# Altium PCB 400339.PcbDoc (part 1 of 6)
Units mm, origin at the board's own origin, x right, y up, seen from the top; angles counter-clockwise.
Board outline 146 x 63.5 mm, 4 copper layers (Top Layer, Mid-Layer 1, Mid-Layer 2, Bottom Layer), stack 1.505 mm thick; 400 components, 261 nets, 1523 pads, 1938 vias.
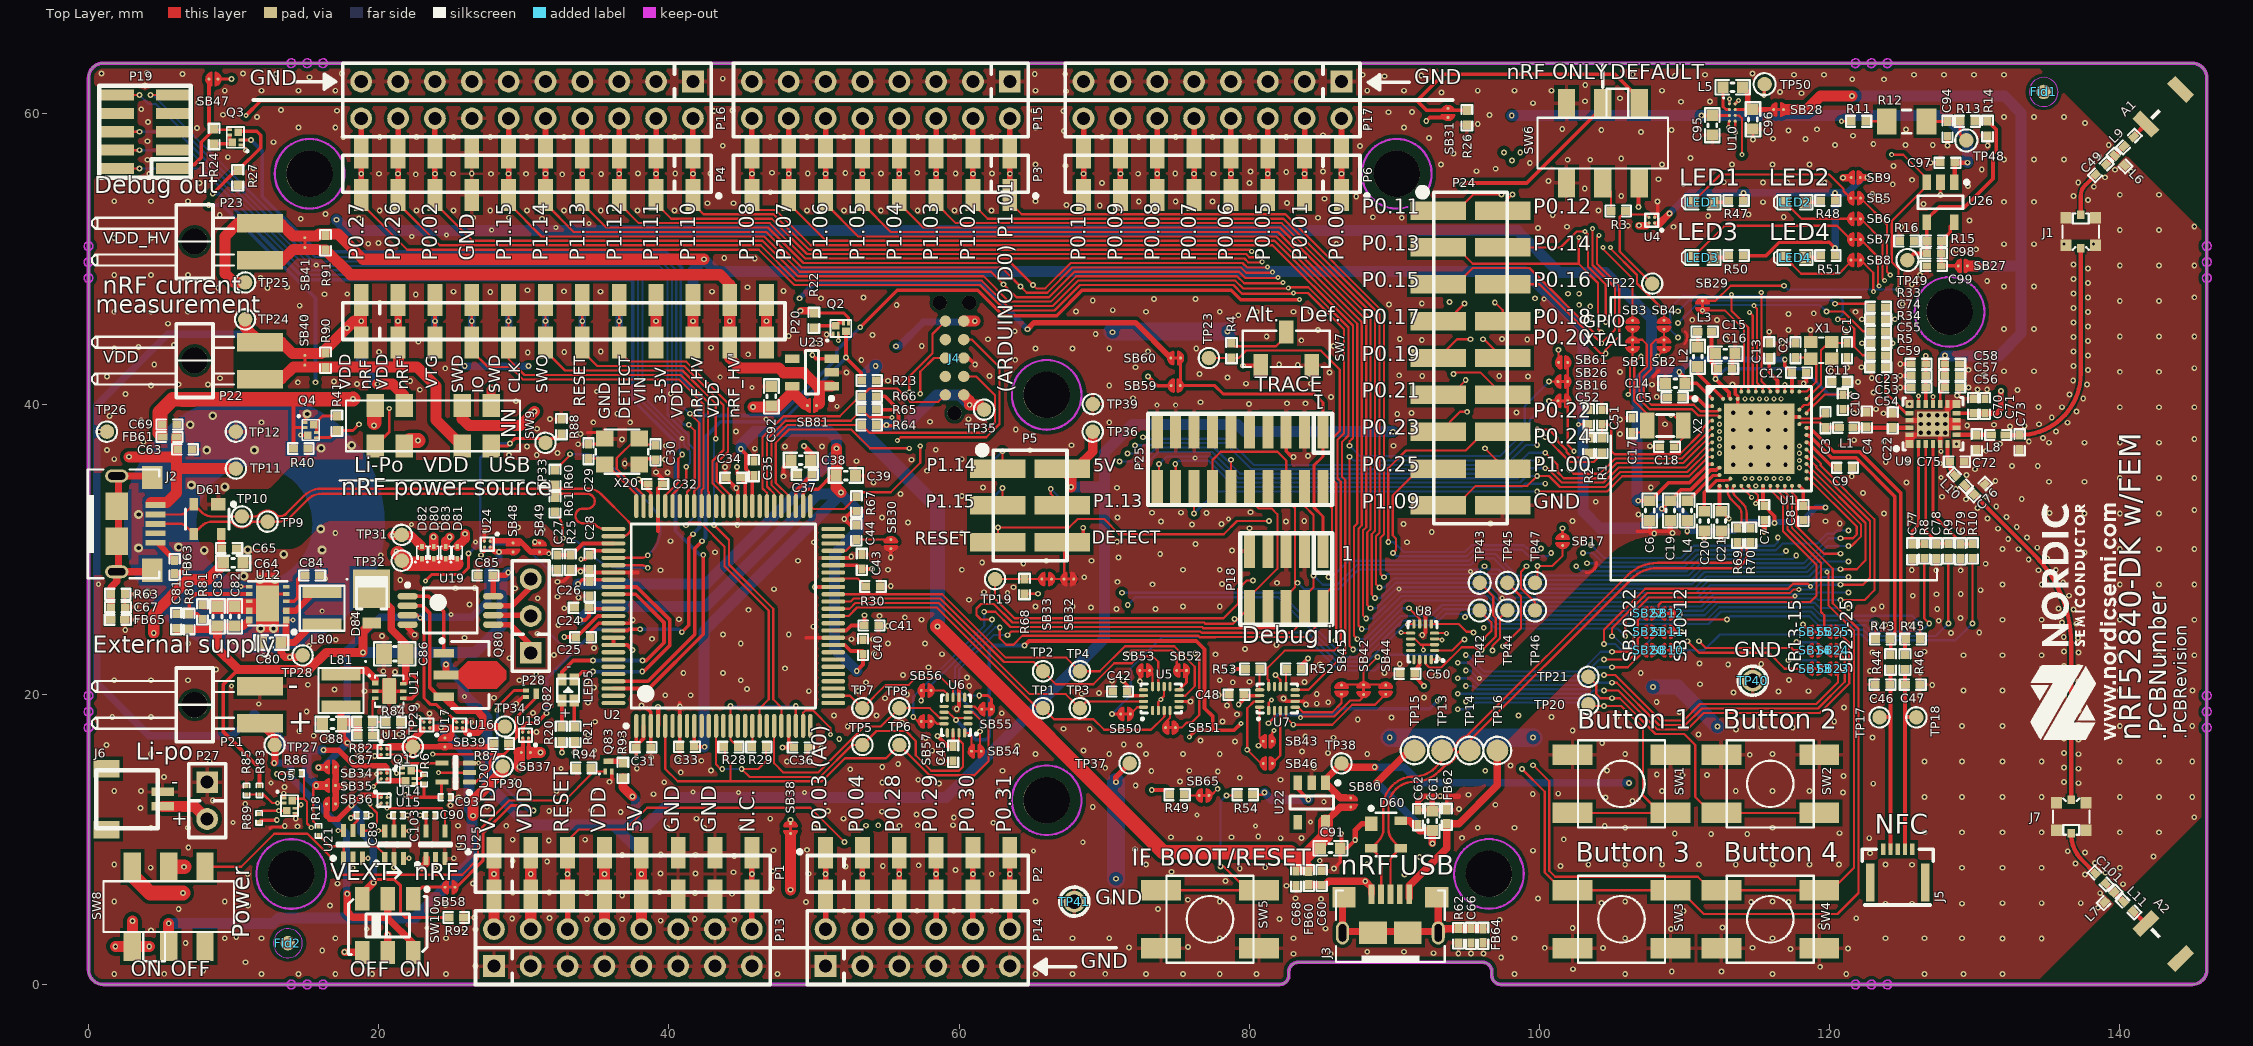
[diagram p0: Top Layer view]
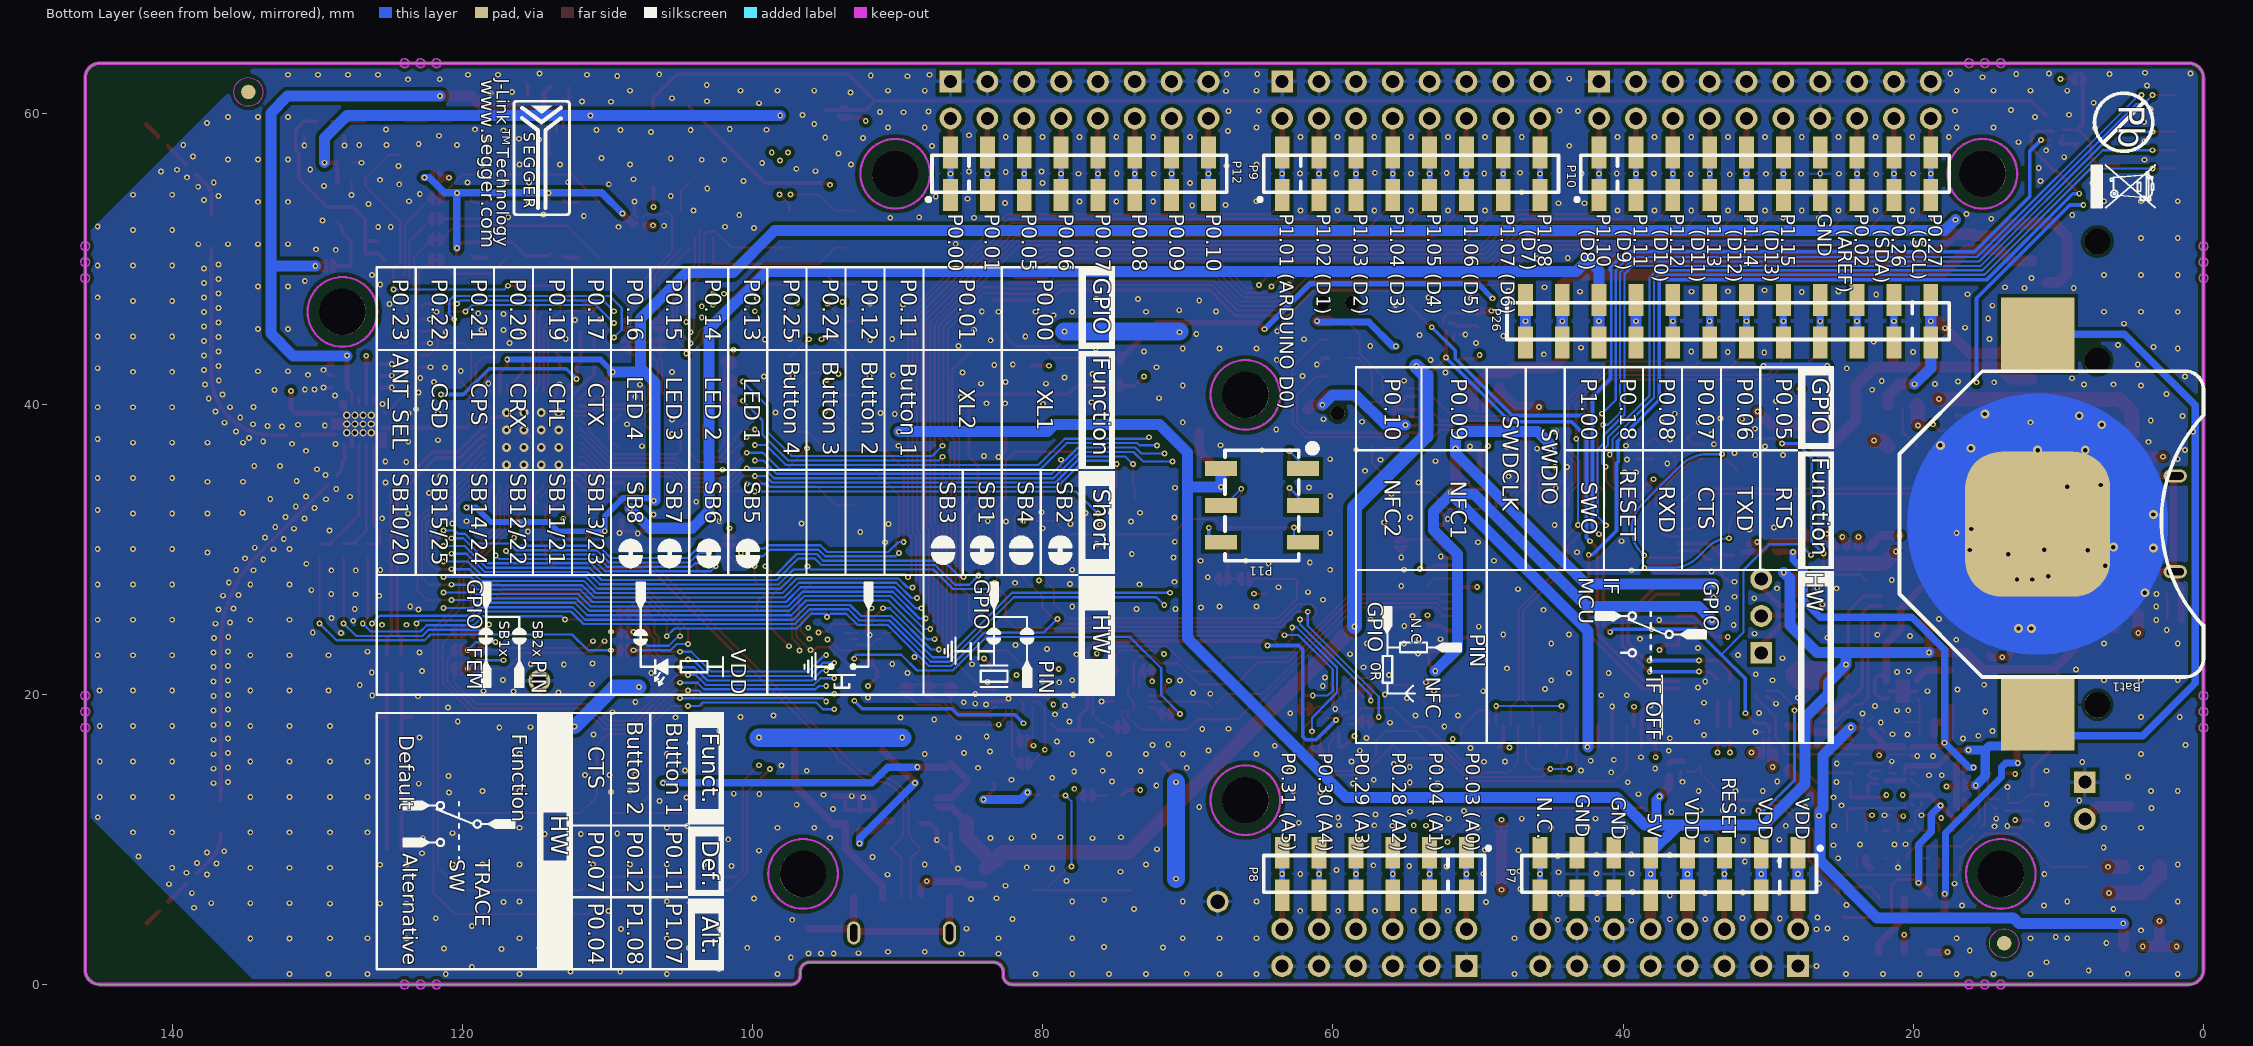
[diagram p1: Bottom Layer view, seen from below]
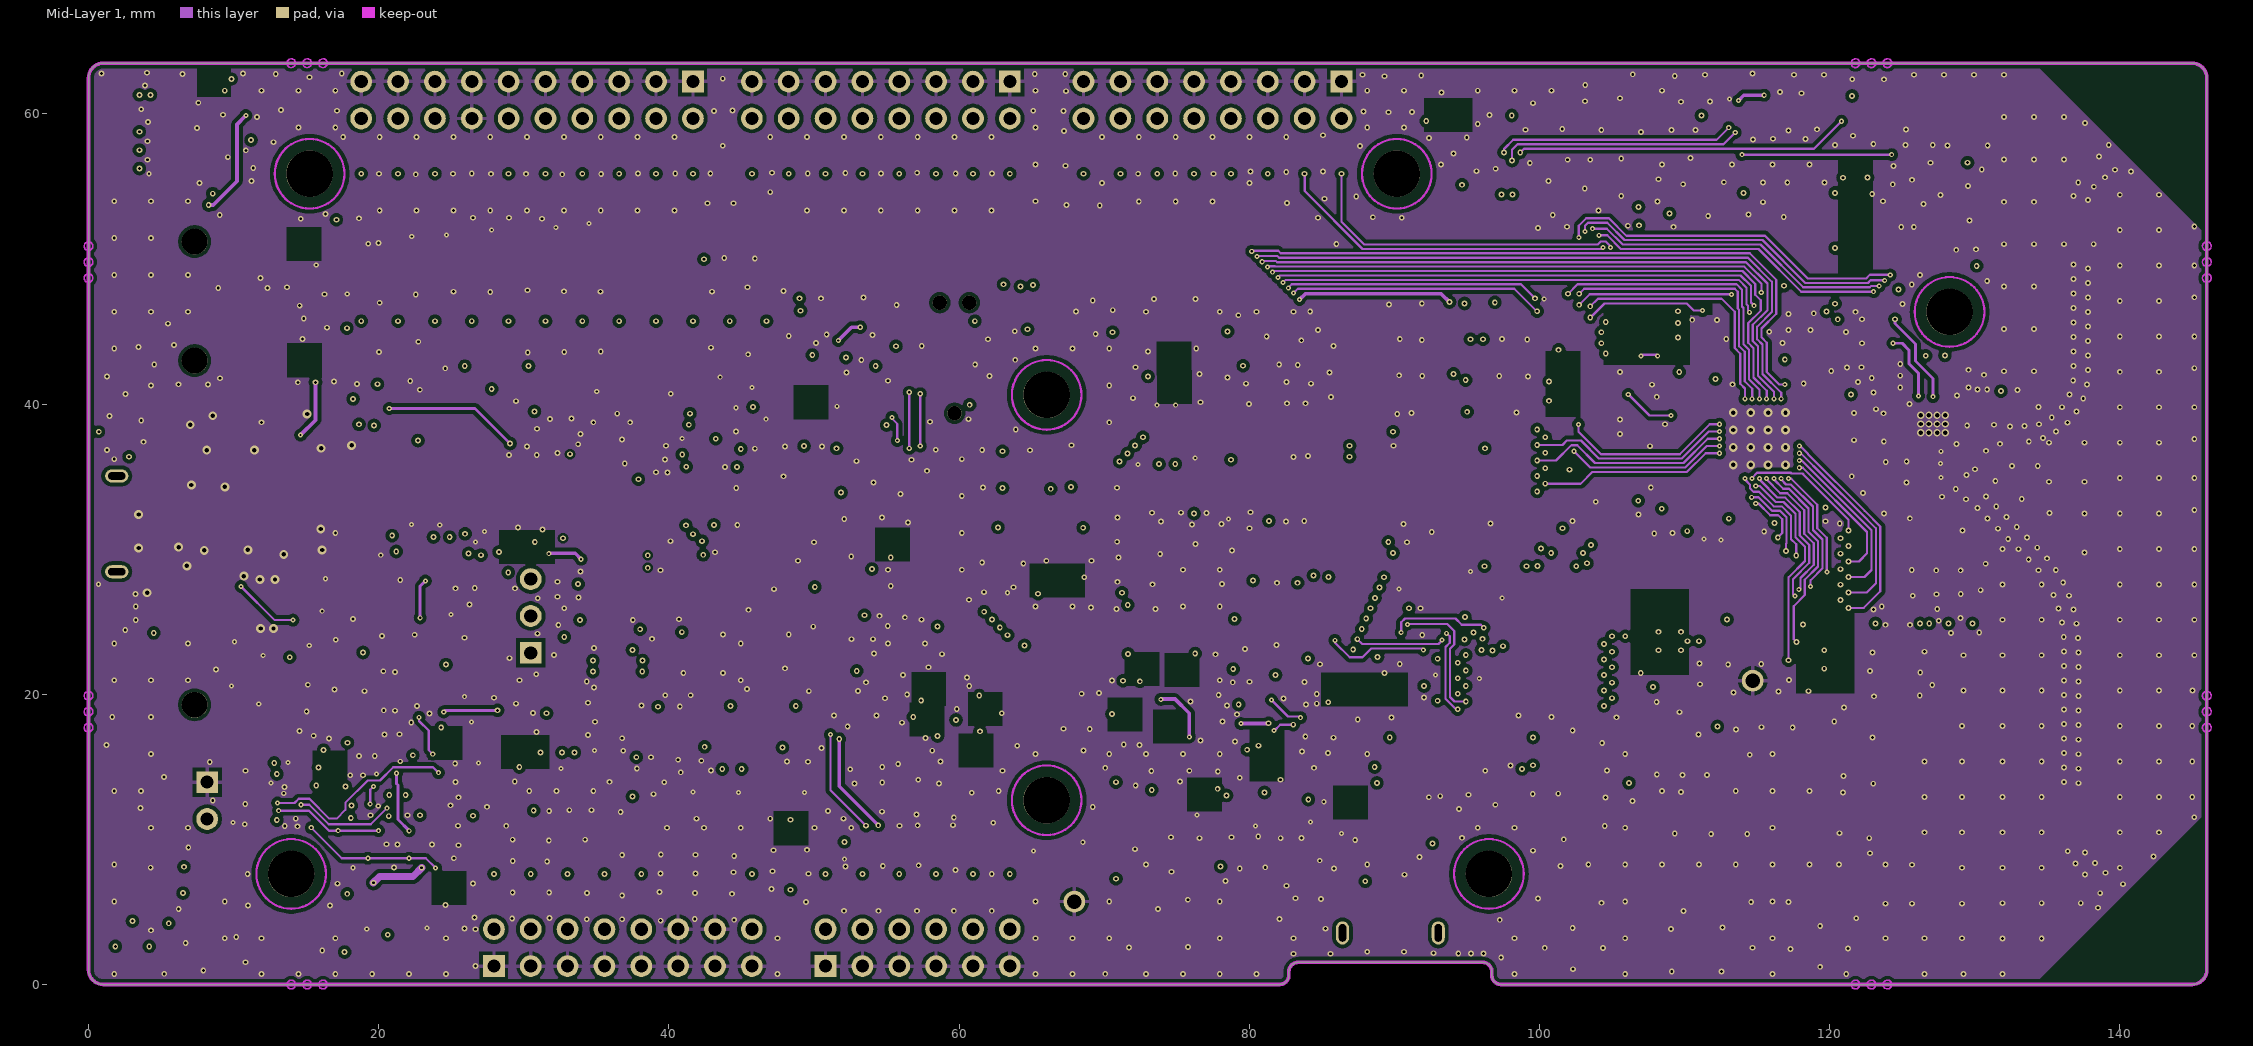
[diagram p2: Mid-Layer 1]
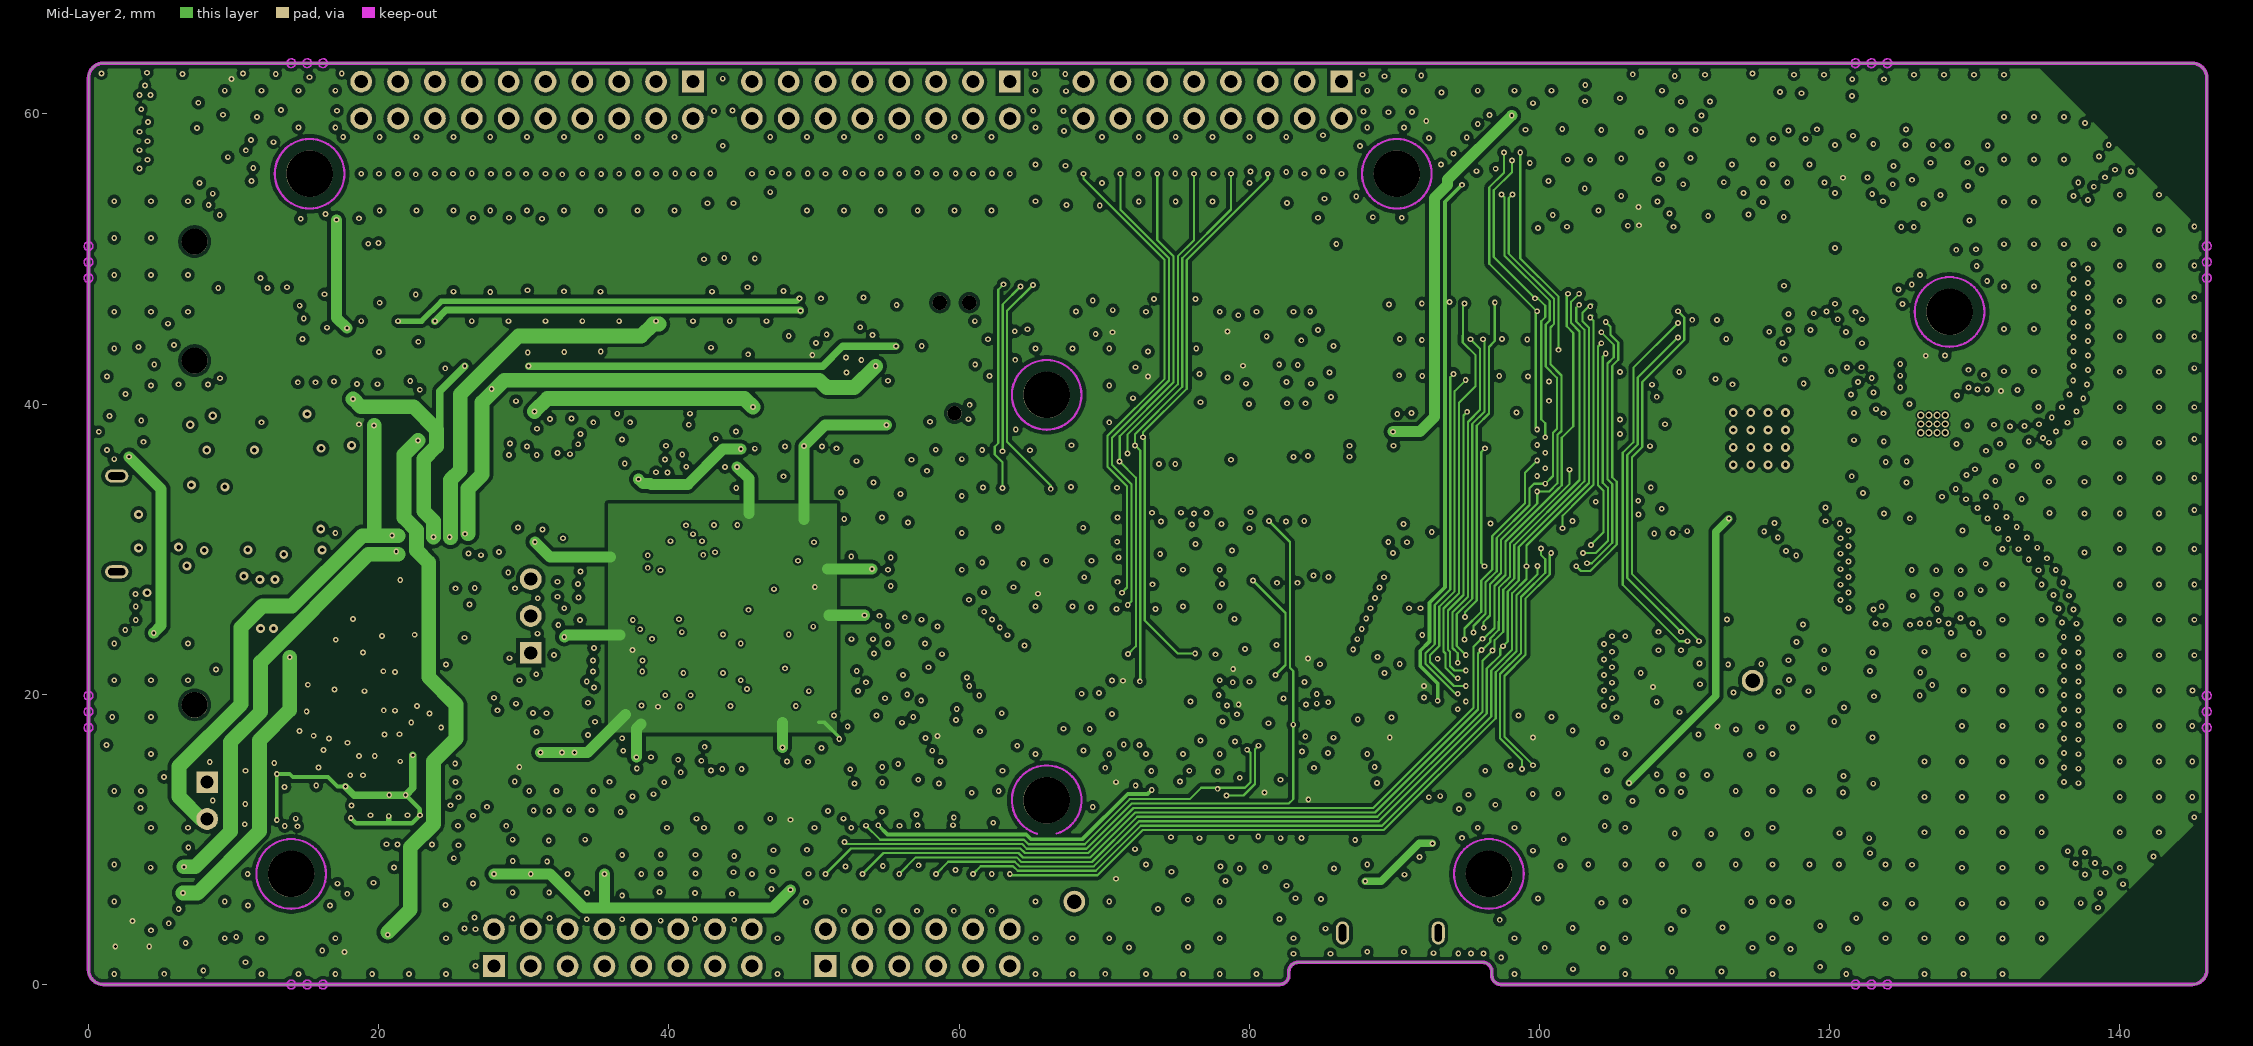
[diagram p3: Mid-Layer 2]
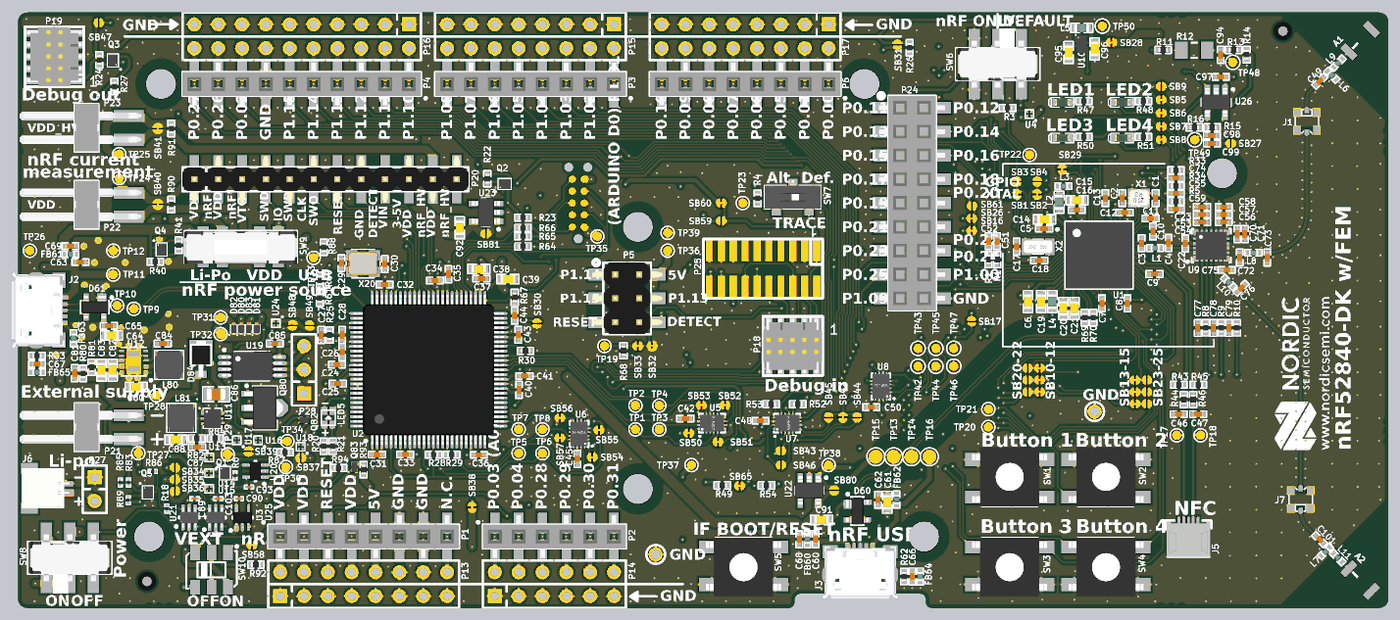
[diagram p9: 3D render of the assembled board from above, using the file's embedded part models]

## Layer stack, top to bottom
Top Solder: solder mask 0.0475, Solder Resist, Dk 3.5
Top Layer: signal copper 0.0175
Dielectric1: prepreg 0.1, FR-4, Dk 3.72
Mid-Layer 1: signal copper 0.035
Dielectric2: core 1.2, FR-4, Dk 3.72
Mid-Layer 2: signal copper 0.035
Dielectric3: prepreg 0.1, FR-4, Dk 3.72
Bottom Layer: signal copper 0.0175
Bottom Solder: solder mask 0.0475, Solder Resist, Dk 3.5

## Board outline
1.016,0 82.099,0 ccw(c82.099,0.635) 82.734,0.635 82.734,0.889 cw(c83.369,0.889) 83.369,1.524 96.09,1.524 cw(c96.09,0.889) 96.725,0.889 96.725,0.635 ccw(c97.36,0.635) 97.36,0 144.984,0 ccw(c144.984,1.016) 146,1.016 146,62.484 ccw(c144.984,62.484) 144.984,63.5 1.016,63.5 ccw(c1.016,62.484) 0,62.484 0,1.016 ccw(c1.016,1.016)

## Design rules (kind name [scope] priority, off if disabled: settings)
Clearance USB_Poly_Clearance [InNamedPolygon('Top_Layer-GND') vs InDifferentialPair('D') or InDifferentialPair('D*')] p1: gap=1.778 ignorepadtopadclearanceinfootprint=FALSE
Clearance "NPTH clearance" [Not PadIsPlated And HoleSize > 0] p2: gap=0.229 ignorepadtopadclearanceinfootprint=FALSE except(0: Arc-Hole Track-Hole SMDPad-Hole THPad-Hole Via-Hole Fill-Hole Poly-Hole Region-Hole Text-Hole)
Clearance USB_Clearance [(InDifferentialPairClass('All Differential Pairs'))] p3: gap=0.152 ignorepadtopadclearanceinfootprint=FALSE except(0: Arc-Hole Track-Hole SMDPad-Hole THPad-Hole Via-Hole Fill-Hole Poly-Hole Region-Hole Text-Hole)
Clearance "U9 Clearence" [HasFootprint('SKY66112-11')] p4: gap=0.102 ignorepadtopadclearanceinfootprint=FALSE
Clearance ANT_Clerance [InNet('RF') or  InNet('NetC72_2') or InNet('NetC73_2') or InNet('NetC49_2') or InNet('ANT1') or  InNet('NetC75_2') or InNet('NetC76_2') or InNet('NetC101_2') or InNet('ANT2')] p5: gap=0.127 ignorepadtopadclearanceinfootprint=FALSE
Clearance Polygon_Clearance [(InNamedPolygon('Top_Layer-GND')) or (InNamedPolygon('Bottom_Layer-GND')) or (InNamedPolygon('Mid_Layer_1-GND')) or (InNamedPolygon('Mid_Layer_2-VDD'))] p6: gap=0.254 ignorepadtopadclearanceinfootprint=FALSE except(0: Arc-Hole Track-Hole SMDPad-Hole THPad-Hole Via-Hole Fill-Hole Poly-Hole Region-Hole Text-Hole)
Clearance SB_Clearance [HasFootprint('Solderbridge') or HasFootprint('QFN40P180X140X55-10N')] p7: gap=0.127 ignorepadtopadclearanceinfootprint=FALSE except(0: Arc-Hole Track-Hole SMDPad-Hole THPad-Hole Via-Hole Fill-Hole Poly-Hole Region-Hole Text-Hole)
Clearance CSP_Clearance [HasFootprint('BGA4C40P2X2_76X76X62')] p8: gap=0.127 ignorepadtopadclearanceinfootprint=FALSE except(0: Arc-Hole Track-Hole SMDPad-Hole THPad-Hole Via-Hole Fill-Hole Poly-Hole Region-Hole Text-Hole)
Clearance P23_Clearance [HasFootprint('FPC_05P-0.5mm-RA-SMD')] p9: gap=0.127 ignorepadtopadclearanceinfootprint=FALSE except(0: Arc-Hole Track-Hole SMDPad-Hole THPad-Hole Via-Hole Fill-Hole Poly-Hole Region-Hole Text-Hole)
Clearance PSON35P100X50-8N_Clearance [HasFootprint('PSON35P100X50-8N')] p10: gap=0.15 ignorepadtopadclearanceinfootprint=FALSE except(0: Arc-Hole Track-Hole SMDPad-Hole THPad-Hole Via-Hole Fill-Hole Poly-Hole Region-Hole Text-Hole)
Clearance Top_layer_Clearance [All vs OnLayer('Top Layer')] p11: gap=0.145 ignorepadtopadclearanceinfootprint=FALSE
Clearance [All] p12: gap=0.15 ignorepadtopadclearanceinfootprint=FALSE except(0: Arc-Hole Track-Hole SMDPad-Hole THPad-Hole Via-Hole Fill-Hole Poly-Hole Region-Hole Text-Hole)
ComponentClearance [All] p1 off: gap=0.254 collisioncheckmode=3 verticalgap=0.254 showdistances=FALSE
DiffPairsRouting [All] p1: maxlimit=0.193 minlimit=0.191 mostfreqgap=0.193 toplayer_minwidth=0.165 toplayer_maxwidth=0.165 toplayer_prefwidth=0.165 midlayer1_minwidth=0.165 midlayer1_maxwidth=0.165 midlayer1_prefwidth=0.165 midlayer2_minwidth=0.165 midlayer2_maxwidth=0.165 midlayer2_prefwidth=0.165 bottomlayer_minwidth=0.165 bottomlayer_maxwidth=0.165 bottomlayer_prefwidth=0.165 maxuncoupledlength=12.7
FabricationTestPointUsage TestPointUsage [All] p1: valid=0 allowmultiple=FALSE
FabricationTestpoint Testpoint [All] p1: side=3 testpointundercomponent=TRUE minsize=1.016 maxsize=2.54 preferedsize=1.524 minholesize=0 maxholesize=1.016 preferedholesize=0.813 testpointgrid=0.025 allowsidetop=TRUE allowsidebottom=TRUE usegrid=TRUE gridtolerance=0
Height [All] p1 off: minheight=0 maxheight=25.4 prefheight=12.7
HoleSize [All] p1: absolutevalues=TRUE maxlimit=5 minlimit=0.15 maxpercent=80.000 minpercent=20.000
MinimumAnnularRing [All] p1 off: minimumring=0.152
NetAntennae NetAntennae_ANT [InNet('ANT')] p1: netantennaetolerance=40
NetAntennae [All] p2 off: netantennaetolerance=0
PolygonConnect PolygonConnect_1 [isVia and innet(gnd) or isVia and innet('VDD') or HasFootprint('COAXIAL-SWF') or isVia and innet('VDD_SAM') or HasFootprint('SKY66112-11') or InComponent('C4') or InComponent('C22') or InComponent('C49') or InComponent('C72') or InComponent('C73') or InComponent('C75') or InComponent('C76') or InComponent('C100') or InComponent('L6') or InComponent('L7')] p1: connectstyle=Direct reliefconductorwidth=0.254 reliefentries=4 polygonreliefangle="90 Angle" airgapwidth=0.254
PolygonConnect [All] p2: connectstyle=Relief reliefconductorwidth=0.254 reliefentries=4 polygonreliefangle="90 Angle" airgapwidth=0.254
RoutingVias [All] p1: holewidth=0.305 width=0.61 viastyle="Through Hole" minholewidth=0.15 minwidth=0.35 maxholewidth=0.305 maxwidth=0.61 useviatemplates=TRUE viatemplateguid#1={15613F6C-49F0-45F4-A731-D8DDC1FA751F} viatemplateguid#2={417C15BB-06C3-4683-8E82-7D7C75B66497} viatemplatename#1=v35h15m0 viatemplatename#2=v40h20m0mx0
SilkToSolderMaskClearance SilkscreenOverComponentPads [IsPad] p1: minsilkscreentomaskgap=0.254 clearancetoexposedcopper=TRUE
SolderMaskExpansion [All] p1: expansion=0.076
UnpouredPolygon [All] p1 off:
Width Width_Diff [(InDifferentialPairClass('All Differential Pairs'))] p1: maxlimit=0.165 minlimit=0.165 preferedwidth=0.165
Width [All] p2: maxlimit=10.16 minlimit=0.145 preferedwidth=0.152 midlayer1_minwidth=0.152 midlayer2_minwidth=0.152 bottomlayer_minwidth=0.152 minimp=50.000000 maximp=50.000000 favimp=50.000000
21 further rules are at their usual default settings.

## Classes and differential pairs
component class pca10084_sheet8_skyworks: A1 A2 C23 C49 C53 C54 C55 C56 C57 C58 C59 C70 C71 C72 C73 C74 C75 C76 C77 C78 C79 C94 C95 C96 C97 C98 C99 C101 J1 J7 L5 L6 L7 L8 L9 L10 L11 R5 R8 R9 R10 R11 R12 R13 R14 R15 R16 R33 R34 SB27 SB28 TP48 TP49 TP50 U9 U10 U26
component class pca10084_sheet7_power_supply: Bat1 C80 C81 C82 C83 C84 C85 C86 C87 C88 C89 C90 C91 C92 C93 C103 D80 D81 D82 D83 D84 L80 L81 P21 P22 P23 Q1 Q5 Q80 Q82 Q83 R6 R18 R80 R81 R82 R83 R84 R85 R86 R87 R88 R89 R90 R91 R92 R93 R94 SB34 SB35 SB36 SB37 SB38 SB39 SB40 SB41 SB48 SB58 SB80 SB81 SW8 SW9 SW10 TP24 TP25 TP26 TP27 TP28 TP29 TP30 TP32 TP33 TP34 TP35 TP36 TP37 TP38 TP39 TP40 TP41 U3 U11 U12 U13 U14 U15 U16 U17 U18 U19 U20 U21 U22 U23 U24 U25
component class pca10084_sheet6_connectors: C60 C61 C62 C63 C64 C65 C66 C67 C68 C69 D60 D61 FB60 FB61 FB62 FB63 FB64 FB65 J2 J3 J4 J5 J6 P1 P2 P3 P4 P5 P6 P7 P8 P9 P10 P11 P12 P13 P14 P15 P16 P17 P18 P19 P20 P24 P25 P26 P27 R60 R61 R62 R63 R64 R65 R66 R67 R68 R69 R70 SB32 SB33 SB47 SB59 SB60 TP9 TP10 TP11 TP12 TP13 TP14 TP15 TP16 TP17 TP18 TP19 TP31 TP42 TP43 TP44 TP45 TP46 TP47
component class pca10084_sheet5_misc: C42 C45 C46 C47 C48 C50 LED1 LED2 LED3 LED4 P28 Q4 R3 R4 R26 R40 R41 R43 R44 R45 R46 R47 R48 R50 R51 R52 R53 R54 SB5 SB6 SB7 SB8 SB9 SB31 SB42 SB43 SB44 SB45 SB46 SB50 SB51 SB52 SB53 SB54 SB55 SB56 SB57 SW1 SW2 SW3 SW4 SW5 SW6 SW7 TP1 TP2 TP3 TP4 TP5 TP6 TP7 TP8 TP20 TP21 TP22 TP23 U4 U5 U6 U7 U8
component class pca10084_sheet4_interface_mcu: C24 C25 C26 C27 C28 C29 C30 C31 C32 C33 C34 C35 C36 C37 C38 C39 C40 C41 C43 C44 LED5 Q2 Q3 R20 R21 R22 R23 R24 R25 R27 R28 R29 R30 R49 SB30 SB49 SB65 U2 X20
component class pca10084_sheet3_pin_map: C51 C52 R1 R2 SB10 SB11 SB12 SB13 SB14 SB15 SB16 SB17 SB20 SB21 SB22 SB23 SB24 SB25 SB26 SB29 SB61
component class pca10084_sheet2_nrf52840_mcu: C1 C2 C3 C4 C5 C6 C7 C8 C9 C10 C11 C12 C13 C14 C15 C16 C17 C18 C19 C20 C21 C22 L1 L2 L3 L4 SB1 SB2 SB3 SB4 U1 X1 X2
component class pca10084_sheet1_cover: Fid1 Fid2
differential pair D: +D_P -D_N
differential pair D*: +D*_P -D*_N
differential pair DHSD: +DHSD_P -DHSD_N
differential pair DFSD: +DFSD_P -DFSD_N

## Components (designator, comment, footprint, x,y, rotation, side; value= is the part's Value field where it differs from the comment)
A1 "2450AT18B100" 2450AT18B100#1 143,60.5 r45 top locked
A2 "2450AT18B100" 2450AT18B100#2 143,3 r315 top locked
Bat1 "Bat Holder CR2032" CR2032_HOLDER_SMD 11.43,31.735 r270 bottom locked
C1 "12pF" CAPC1005X04L 121.203,43.713 r270 top
C2 "12pF" CAPC1005X04L 117.647,43.713 r90 top
C3 "1.0pF" CAPC1005X04L 119.715,38.893 r270 top
C4 "1.0pF" CAPC1005X04L 122.57,38.938 r270 top
C5 "100nF" CAPC1005X04L 109.324,40.455 r180 top
C6 "4.7µF" CAPC1608X06L 107.613,32.667 r270 top
C7 "100nF" CAPC1005X04L 115.49,32.492 r270 top
C8 "100nF" CAPC1005X04L 118.189,32.492 r270 top
C9 "820pF" CAPC1005X04L 121.064,35.617 r0 top
C10 "N.C." CAPC1005X04L 120.919,40.157 r90 top
C11 "100pF" CAPC1005X04L 120.664,41.542 r0 top
C12 "100nF" CAPC1005X04L 117.889,42.167 r0 top
C13 "N.C." CAPC1005X04L 115.839,43.717 r90 top
C14 "1.0µF" CAPC1608X06L 109.364,41.444 r180 top
C15 "1.0µF" CAPC1608X06L 112.814,43.481 r180 top
C16 "47nF" CAPC1005X04L 112.801,42.443 r0 top
C17 "12pF" CAPC1005X04L 106.385,38.55 r270 top
C18 "12pF" CAPC1005X04L 108.798,37.052 r0 top
C19 "4.7µF" CAPC1608X06L 109.014,32.667 r270 top
C20 "4.7µF" CAPC1608X06L 111.364,31.942 r270 top
C21 "4.7µF" CAPC1608X06L 112.539,31.942 r270 top
C22 "N.C." CAPC1005X04L 124.356,38.884 r90 top
C23 "4.7µF" CAPC1005X04L 126.128,42.774 r0 top
C24 "100nF" CAPC1005X04L 34.001,25.959 r0 top
C25 "100nF" CAPC1005X04L 34.077,23.927 r180 top
C26 "100nF" CAPC1005X04L 34.534,27.28 r90 top
C27 "10pF" CAPC1005X04L 32.324,29.108 r90 top
C28 "100nF" CAPC1005X04L 34.534,29.108 r90 top
C29 "18pF" CAPC1005X04L 34.458,36.754 r90 top
C30 "18pF" CAPC1005X04L 39.081,36.678 r270 top
C31 "100nF" CAPC1005X04L 38.242,16.358 r180 top
C32 "100nF" CAPC1005X04L 39.055,34.493 r0 top
C33 "100nF" CAPC1005X04L 41.25,16.383 r0 top
C34 "100nF" CAPC1005X04L 44.44,34.925 r0 top
C35 "100nF" CAPC1005X04L 45.862,35.585 r270 top
C36 "100nF" CAPC1005X04L 49.098,16.332 r180 top
C37 "100nF" CAPC1005X04L 49.368,35.128 r0 top
C38 "10µF" CAPC1608X06L 49.088,36.144 r0 top
C39 "10µF" CAPC1608X06L 52.197,35.077 r180 top
C40 "100nF" CAPC1005X04L 53.381,23.266 r270 top
C41 "100nF" CAPC1005X04L 53.965,24.74 r180 top
C42 "100nF" CAPC1005X04L 71.095,20.193 r0 top
C43 "100nF" CAPC1005X04L 53.305,29.134 r270 top
C44 "10nF" CAPC1005X04L 52.924,31.166 r270 top
C45 "100nF" CAPC1005X04L 59.588,15.9 r90 top
C46 "300pF" CAPC1005X04L 123.647,20.669 r180 top
C47 "300pF" CAPC1005X04L 125.73,20.669 r180 top
C48 "100nF" CAPC1005X04L 79.121,19.964 r0 top
C49 "1.0pF" CAPC1005X04L 138.695,56.17 r225 top
C50 "100nF" CAPC1005X04L 90.907,21.412 r0 top
C51 "N.C." CAPC1005X04L 104.318,39.116 r270 top
C52 "N.C." CAPC1005X04L 103.403,39.116 r90 top
C53 "100nF" CAPC1005X04L 126.128,41.961 r0 top
C54 "1.0nF" CAPC1005X04L 126.128,41.148 r0 top
C55 "1.0nF" CAPC1005X04L 123.356,44.197 r0 top
C56 "1.0nF" CAPC1005X04L 128.448,41.148 r180 top
C57 "100nF" CAPC1005X04L 128.448,41.961 r180 top
C58 "4.7µF" CAPC1005X04L 128.448,42.774 r180 top
C59 "1.0nF" CAPC1005X04L 123.356,42.543 r0 top
C60 "10nF" CAPC1005X04L 84.995,7.341 r270 top
C61 "10µF" CAPC1608X06L 92.623,11.278 r270 top
C62 "100nF" CAPC1005X04L 91.632,11.532 r270 top
C63 "10nF" CAPC1005X04L 6.655,36.881 r0 top
C64 "10µF" CAPC1608X06L 9.972,29.058 r180 top
C65 "100nF" CAPC1005X04L 9.693,30.074 r180 top
C66 "100nF" CAPC1005X04L 95.282,3.355 r90 top
C67 "100nF" CAPC1005X04L 2.028,26.01 r180 top
C68 "100nF" CAPC1005X04L 83.223,7.328 r90 top
C69 "100nF" CAPC1005X04L 5.578,38.6 r180 top
C70 "1.0nF" CAPC1005X04L 129.896,39.878 r270 top
C71 "100nF" CAPC1005X04L 130.708,39.878 r270 top
C72 "1.0pF" CAPC1005X04L 130.15,37.372 r90 top
C73 "1.0pF" CAPC1005X04L 133.096,37.372 r90 top
C74 "1.0nF" CAPC1005X04L 123.356,45.851 r0 top
C75 "1.0pF" CAPC1005X04L 128.775,36.043 r180 top
C76 "1.0pF" CAPC1005X04L 130.327,34.118 r225 top
C77 "1.0nF" CAPC1005X04L 125.696,29.858 r90 top
C78 "1.0nF" CAPC1005X04L 127.356,29.858 r90 top
C79 "1.0nF" CAPC1005X04L 129.015,29.858 r90 top
C80 "10µF" CAPC1608X06L 12.598,23.571 r0 top
C81 "15pF" CAPC1005X04L 6.045,25.044 r270 top
C82 "10µF" CAPC1608X06L 10.084,25.375 r270 top
C83 "10µF" CAPC1608X06L 8.89,25.375 r270 top
C84 "470nF" CAPC1005X04L 15.418,28.194 r180 top
C85 "100nF" CAPC1005X04L 27.356,28.194 r0 top
C86 "4.7µF" CAPC2012X11L 21.107,22.784 r0 top
C87 "150pF" CAPC1005X04L 19.075,17.17 r180 top
C88 "10µF" CAPC1608X06L 16.815,17.958 r0 top
C89 "100nF" CAPC0603X03L_C 18.82,11.664 r180 top
C90 "100nF" CAPC0603X03L_C 23.554,11.664 r180 top
C91 "1.0µF" CAPC1608X06L 85.598,9.398 r180 top
C92 "1.0µF" CAPC1608X06L 47.066,40.538 r270 top
C93 "100nF" CAPC0603X03L_C 24.621,12.902 r180 top
C94 "10nF" CAPC1005X04L 128.127,58.975 r90 top
C95 "10µF" CAPC1608X06L 111.922,59.221 r90 top
C96 "10µF" CAPC1608X06L 114.717,59.627 r90 top
C97 "1.0µF" CAPC1005X04L 128.131,56.635 r0 top
C98 "TBD" CAPC1005X04L 127.191,50.387 r0 top
C99 "4.7µF" CAPC1005X04L 127.191,49.523 r0 top
C101 "1.0pF" CAPC1005X04L 138.67,7.305 r135 top
C103 "100nF" CAPC0603X03L_C 21.336,11.664 r180 top
D60 "PRTR5V0U2X" SOT190P230X110-4L 89.427,10.34 r0 top
D61 "PRTR5V0U2X" SOT190P230X110-4L 8.194,32.08 r270 top
D80 "NSR0620P2T5G" SODFL100X40-2N 23.8,29.766 r90 top
D81 "NSR0620P2T5G" SODFL100X40-2N 25.425,29.766 r90 top
D82 "NSR0620P2T5G" SODFL100X40-2N 22.987,29.766 r90 top
D83 "NSR0620P2T5G" SODFL100X40-2N 24.613,29.766 r90 top
D84 "MBRM110E" DO-216AA 19.507,26.568 r270 top
FB60 "120R/0.55A" INDC1005X04L 84.106,7.341 r90 top
FB61 "120R/0.55A" INDC1005X04L 5.585,37.734 r180 top
FB62 "120R/0.55A" INDC1005X04L 93.614,11.558 r90 top
FB63 "120R/0.55A" INDC1005X04L 5.933,28.779 r270 top
FB64 "120R/0.55A" INDC1005X04L 96.12,3.355 r270 top
FB65 "120R/0.55A" INDC1005X04L 2.021,25.139 r0 top
Fid1 "Fiducial mark" Fiducial 134.753,61.515 r180 top
Fid2 "Fiducial mark" Fiducial 13.743,2.845 r0 top
J1 "MM8130-2600" COAXIAL-SWF 137.313,51.892 r180 top
J2 "MicroUSB-B" USB-Micro-B-RA-SMD-PiP 4.619,31.75 r0 top
J3 "MicroUSB-B" USB-Micro-B-RA-SMD-PiP 89.729,6.232 r90 top
J4 "TC2050-IDC" TC2050-IDC-NLFP 59.69,43.18 r90 top
J5 "FPC 0.5mm RA SMD" FPC_05P-0.5mm-RA-SMD 123.698,9.328 r0 top
J6 "HDR-2, 1mm" SM02B-SRSS-TB 5.105,12.776 r270 top
J7 "MM8130-2600" COAXIAL-SWF 136.654,11.571 r0 top
L1 "3.9nH" INDC1005X04L 121.138,38.385 r0 top
L2 "10µH" INDC1608X06L 110.914,43.267 r270 top
L3 "15nH" INDC1005X04L 111.389,44.992 r180 top
L4 "10µH" INDC1608X06L 110.189,32.667 r90 top
L5 "1µH" INDC1608X06L 113.319,61.837 r0 top
L6 "2.7nH" INDC1005X04L 139.99,56.793 r135 top
L7 "2.7nH" INDC1005X04L 139.293,6.01 r45 top
L8 "3.0nH" INDC1005X04L 131.626,37.876 r0 top
L9 "3.3nH" INDC1005X04L 140.629,58.104 r45 top
L10 "3.0nH" INDC1005X04L 128.99,34.732 r315 top
L11 "3.3nH" INDC1005X04L 140.604,5.371 r315 top
L80 "2.2µH" TY-NR3015 16.104,25.933 r270 top
L81 "4.7µH" TY-NR3015 17.399,20.269 r270 top
LED1 "L0603G" LED_0603_G 111.273,53.917 r0 top
LED2 "L0603G" LED_0603_G 117.623,53.917 r0 top
LED3 "L0603G" LED_0603_G 111.273,50.107 r0 top
LED4 "L0603G" LED_0603_G 117.623,50.107 r0 top
LED5 "LED RG" LED_DUAL_0606 33.061,20.295 r180 top
P1 "Socket 1x8" SOCKET_1x8_SMD 27.94,7.62 r0 top locked
P2 "Socket 1x6" SOCKET_1x6_SMD 50.8,7.62 r0 top locked
P3 "Socket 1x8" SOCKET_1x8_SMD 63.5,55.88 r180 top locked
P4 "Socket 1x10" SOCKET_1x10_SMD 41.656,55.88 r180 top locked
P5 "Pin Hdr 2x3" HDR_2x3-SMD 64.897,33.02 r270 top locked
P6 "Socket 1x8" SOCKET_1x8_SMD 86.36,55.88 r180 top locked
P7 "Pin List 1x8" LIST_1x8_SMD-NC 27.94,7.62 r0 bottom locked
P8 "Pin List 1x6" LIST_1x6_SMD-NC 50.8,7.62 r0 bottom locked
P9 "Pin List 1x8" LIST_1x8_SMD-NC 63.5,55.88 r180 bottom locked
P10 "Pin List 1x10" LIST_1x10_SMD-NC 41.656,55.88 r180 bottom locked
P11 "Socket 2x3" SOCKET_2x3_SMD-2.54mm-bottom-NC 64.897,33.02 r270 top locked
P12 "Pin List 1x8" LIST_1x8_SMD-NC 86.36,55.88 r180 bottom locked
P13 "Pin Header 2x8" HDR_2x8-NC 36.83,2.54 r0 top locked
P14 "Pin Header 2x6" HDR_2x6-NC 57.15,2.54 r0 top locked
P15 "Pin Header 2x8" HDR_2x8-NC 54.61,60.96 r180 top locked
P16 "Pin Header 2x10" HDR_2x10-NC 30.226,60.96 r180 top locked
P17 "Pin Header 2x8" HDR_2x8-NC 77.47,60.96 r180 top locked
P18 "Pin Header 2x5, 1.27mm" HDR_2x5-SMD-1.27mm-K 82.55,27.94 r180 top locked
P19 "Pin Header 2x5, 1.27mm" HDR_2x5-SMD-1.27mm-K 3.886,58.776 r90 top
P20 "Pin List 1x12" LIST_1x12_SMD 18.796,45.72 r0 top locked
P21 "Pin List 1x2, Angled" LIST_ANG_1x2-SMD-2.54MM 11.811,19.279 r270 top
P22 "Pin List 1x2, Angled" LIST_ANG_1x2-SMD-2.54MM 11.811,43 r270 top
P23 "Pin List 1x2, Angled" LIST_ANG_1x2-SMD-2.54MM 11.811,51.2 r270 top
P24 "Socket 2x9" SOCKET_2x9_SMD-2.54mm 95.25,43.18 r270 top locked
P25 "Pin Header 2x10, 1.27mm" HDR_2x10-SMD-1.27mm-NC 79.375,36.195 r180 top locked
P26 "Socket 1x12" LIST_1x12_SMD-NC 18.796,45.72 r0 bottom locked
P27 "Pin List 1x2" LIST_1x2-NC 8.179,12.675 r270 top locked
P28 "Pin List 1x3" LIST_1x3-NC 30.48,25.4 r90 top locked
Q1 "DMC3730UFL3-7" DMC3730UFL3-7 22.047,14.381 r0 top
Q2 "DMC3730UFL3-7" DMC3730UFL3-7 51.857,45.213 r90 top
Q3 "DMC3730UFL3-7" DMC3730UFL3-7 10.119,58.384 r180 top
Q4 "DMC3730UFL3-7" DMC3730UFL3-7 15.316,38.217 r0 top
Q5 "DMN1150UFL3" X2DFN35P100X130X35-6N 13.85,12.331 r0 top
Q80 "FCX690BTA" SOT89-150P409X160-3N 26.289,21.336 r0 top
Q82 "RV2C010UNT2L" DFN65P100X40-3L 30.505,20.041 r0 top
Q83 "RV2C010UNT2L" DFN65P100X40-3L 35.839,15.037 r90 top
R1 "0R" RESC1005X04L 104.318,37.16 r90 top
R2 "0R" RESC1005X04L 103.403,37.16 r90 top
R3 "10k" RESC1005X04L 105.435,53.315 r180 top
R4 "10k" RESC1005X04L 78.791,43.688 r90 top
R5 "1k" RESC1005X04L 123.356,43.369 r0 top
R6 "1M0" RESC0603X03L_C 23.129,14.14 r90 top
R8 "1k" RESC1005X04L 126.526,29.883 r90 top
R9 "1k" RESC1005X04L 128.185,29.883 r90 top
R10 "1k" RESC1005X04L 129.845,29.883 r90 top
R11 "39k" RESC1005X04L 121.998,59.5 r0 top
R12 "0R" RESC3216X08N 125.308,59.475 r0 top
R13 "39k" RESC1005X04L 129.499,59.5 r180 top
R14 "TBD" RESC1005X04L 130.896,59 r90 top
R15 "100k" RESC1005X04L 127.216,51.25 r0 top
R16 "39k" RESC1005X04L 125.329,51.25 r0 top
R18 "100k" RESC0603X03L_C 15.85,10.592 r270 top
R20 "220R" RESC1005X04L 32.585,17.247 r270 top
R21 "220R" RESC1005X04L 33.537,17.247 r270 top
R22 "10k" RESC1005X04L 49.996,45.771 r270 top
R23 "10k" RESC1005X04L 53.797,41.631 r180 top
R24 "10k" RESC1005X04L 8.661,58.445 r270 top
R25 "6k8" RESC1005X04L 33.213,29.108 r90 top
R26 "47k" RESC1005X04L 94.996,59.741 r270 top
R27 "10k" RESC1005X04L 10.287,55.601 r90 top
R28 "150R" RESC1005X04L 44.272,16.358 r180 top
R29 "150R" RESC1005X04L 46.203,16.358 r0 top
R30 "0R" RESC1005X04L 54.067,27.432 r180 top
R33 "1k" RESC1005X04L 123.356,46.678 r0 top
R34 "1k" RESC1005X04L 123.356,45.024 r0 top
R40 "150k" RESC1005X04L 14.63,36.932 r0 top
R41 "1M0" RESC1005X04L 17.12,38.684 r90 top
R43 "N.C." RESC1005X04L 123.669,23.8 r0 top
R44 "0R" RESC1005X04L 124.206,22.225 r90 top
R45 "N.C." RESC1005X04L 125.751,23.8 r180 top
R46 "0R" RESC1005X04L 125.197,22.225 r90 top
R47 "220R" RESC1005X04L 113.559,54.044 r0 top
R48 "220R" RESC1005X04L 119.884,54.044 r0 top
R49 "10k" RESC1005X04L 75.032,13.081 r180 top
R50 "220R" RESC1005X04L 113.559,50.234 r0 top
R51 "220R" RESC1005X04L 119.884,50.234 r0 top
R52 "4k7" RESC1005X04L 83.083,21.742 r180 top
R53 "4k7" RESC1005X04L 80.239,21.742 r0 top
R54 "N.C." RESC1005X04L 79.731,13.081 r0 top
R60 "39R" RESC1005X04L 32.157,34.949 r270 top
R61 "39R" RESC1005X04L 32.157,33.063 r90 top
R62 "10k" RESC1005X04L 94.418,3.355 r90 top
R63 "10k" RESC1005X04L 2.028,26.899 r180 top
R64 "4k7" RESC1005X04L 53.797,38.557 r0 top
R65 "4k7" RESC1005X04L 53.797,39.624 r0 top
R66 "4k7" RESC1005X04L 53.797,40.538 r0 top
R67 "4k7" RESC1005X04L 52.924,33.122 r270 top
R68 "1M0" RESC1005X04L 64.516,27.432 r270 top
R69 "0R" RESC1005X04L 113.65,30.958 r270 top
R70 "0R" RESC1005X04L 114.565,30.958 r270 top
R80 "270k" RESC1005X04L 6.934,25.019 r270 top
R81 "30k" RESC1005X04L 7.849,25.679 r270 top
R82 "330k" RESC1005X04L 19.05,18.085 r180 top
R83 "820k" RESC0603X03L_C 11.782,13.386 r270 top
R84 "120k" RESC1005X04L 21.006,18.085 r180 top
R85 "470k" RESC0603X03L_C 10.893,13.386 r90 top
R86 "1M0" RESC0603X03L_C 14.351,14.554 r0 top
R87 "1M0" RESC1005X04L 28.448,16.612 r0 top
R88 "N.C." RESC1005X04L 32.588,38.456 r90 top
R89 "1M0" RESC0603X03L_C 11.76,11.481 r90 top
R90 "N.C." RESC1005X04L 16.332,43.025 r90 top
R91 "N.C." RESC1005X04L 16.332,51.13 r90 top
R92 "10M" RESC1005X04L 25.349,4.623 r0 top
R93 "1k" RESC1005X04L 36.83,14.757 r90 top
R94 "10M" RESC1005X04L 34.138,14.935 r180 top
SB1 "Solderbridge" Solderbridge_Shorted#1 106.426,44.094 r90 top net-tie
SB2 "Solderbridge" Solderbridge_Shorted#1 108.585,44.094 r90 top net-tie
SB3 "Solderbridge" Solderbridge#1 106.426,45.466 r90 top
SB4 "Solderbridge" Solderbridge#2 108.585,45.466 r90 top
SB5 "Solderbridge" Solderbridge_Shorted#1 121.801,54.197 r180 top net-tie
SB6 "Solderbridge" Solderbridge_Shorted#1 121.801,52.774 r180 top net-tie
SB7 "Solderbridge" Solderbridge_Shorted#1 121.801,51.352 r180 top net-tie
SB8 "Solderbridge" Solderbridge_Shorted#1 121.801,49.93 r180 top net-tie
SB9 "Solderbridge" Solderbridge#1 121.802,55.619 r0 top
SB10 "Solderbridge" Solderbridge_Shorted#1 108.839,23.038 r0 top net-tie
SB11 "Solderbridge" Solderbridge_Shorted#1 108.839,24.308 r0 top net-tie
SB12 "Solderbridge" Solderbridge_Shorted#1 108.839,25.578 r0 top net-tie
SB13 "Solderbridge" Solderbridge_Shorted#1 118.999,21.768 r180 top net-tie
SB14 "Solderbridge" Solderbridge_Shorted#1 118.999,23.038 r180 top net-tie
SB15 "Solderbridge" Solderbridge_Shorted#1 118.999,24.308 r180 top net-tie
SB16 "Solderbridge" Solderbridge_Shorted#1 101.613,40.231 r180 top net-tie
SB17 "Solderbridge" Solderbridge#1 101.6,30.573 r270 top
SB20 "Solderbridge" Solderbridge#2 107.569,23.038 r180 top
SB21 "Solderbridge" Solderbridge#3 107.569,24.308 r180 top
SB22 "Solderbridge" Solderbridge#2 107.569,25.578 r180 top
SB23 "Solderbridge" Solderbridge#3 120.269,21.768 r0 top
SB24 "Solderbridge" Solderbridge#3 120.269,23.038 r0 top
SB25 "Solderbridge" Solderbridge#3 120.269,24.308 r0 top
SB26 "Solderbridge" Solderbridge_Shorted#1 101.613,41.555 r180 top net-tie
SB27 "Solderbridge" Solderbridge#4 129.184,49.53 r180 top
SB28 "Solderbridge" Solderbridge_Shorted#1 116.484,60.302 r180 top net-tie
SB29 "Solderbridge" Solderbridge_Shorted#1 111.244,46.783 r90 top net-tie
SB30 "Solderbridge" Solderbridge#2 55.297,30.353 r270 top
SB31 "Solderbridge" Solderbridge#1 93.701,60.071 r90 top
SB32 "Solderbridge" Solderbridge_Shorted#1 67.564,27.94 r180 top net-tie
SB33 "Solderbridge" Solderbridge_Shorted#1 66.04,27.94 r180 top net-tie
SB34 "Solderbridge" Solderbridge#1 16.716,14.986 r180 top
SB35 "Solderbridge" Solderbridge#5 16.713,13.716 r180 top
SB36 "Solderbridge" Solderbridge#1 16.716,12.446 r180 top
SB37 "Solderbridge" Solderbridge#2 30.144,15.992 r180 top
SB38 "Solderbridge" Solderbridge_Shorted#1 48.387,10.744 r90 top net-tie
SB39 "Solderbridge" Solderbridge#5 24.562,16.688 r270 top
SB40 "Solderbridge" Solderbridge_Shorted#1 14.91,43.025 r270 top net-tie
SB41 "Solderbridge" Solderbridge_Shorted#1 14.91,51.13 r270 top net-tie
SB42 "Solderbridge" Solderbridge_Shorted#1 87.884,20.32 r90 top net-tie
SB43 "Solderbridge" Solderbridge#3 81.28,16.764 r0 top
SB44 "Solderbridge" Solderbridge#4 89.408,20.32 r90 top
SB45 "Solderbridge" Solderbridge#3 86.36,20.32 r90 top
SB46 "Solderbridge" Solderbridge#2 81.28,15.24 r180 top
SB47 "Solderbridge" Solderbridge#2 8.611,62.408 r180 top
SB48 "Solderbridge" Solderbridge#3 29.261,30.124 r270 top
SB49 "Solderbridge" Solderbridge#2 31.09,30.124 r270 top
SB50 "Solderbridge" Solderbridge_Shorted#2 71.476,18.644 r0 top net-tie
SB51 "Solderbridge" Solderbridge_Shorted#2 74.574,17.704 r180 top net-tie
SB52 "Solderbridge" Solderbridge_Shorted#2 75.336,21.641 r0 top net-tie
SB53 "Solderbridge" Solderbridge_Shorted#2 72.796,21.641 r0 top net-tie
SB54 "Solderbridge" Solderbridge_Shorted#2 61.189,16.078 r180 top net-tie
SB55 "Solderbridge" Solderbridge_Shorted#2 61.9,18.974 r180 top net-tie
SB56 "Solderbridge" Solderbridge_Shorted#2 57.734,20.269 r0 top net-tie
SB57 "Solderbridge" Solderbridge_Shorted#2 57.734,18.136 r0 top net-tie
SB58 "Solderbridge" Solderbridge_Shorted#1 24.917,6.706 r180 top net-tie
SB59 "Solderbridge" Solderbridge#4 74.93,41.275 r180 top
SB60 "Solderbridge" Solderbridge_Shorted#1 74.93,43.18 r180 top net-tie
SB61 "Solderbridge" Solderbridge#4 101.639,42.879 r180 top
SB65 "Solderbridge" Solderbridge_Shorted#1 76.886,13.03 r180 top net-tie
SB80 "Solderbridge" Solderbridge#1 86.995,12.548 r270 top
SB81 "Solderbridge" Solderbridge#2 49.86,39.903 r180 top
SW1 "PB SW" Switch-PB-6.2x6.3mm-SMD 105.653,13.83 r0 top locked
SW2 "PB SW" Switch-PB-6.2x6.3mm-SMD 115.915,13.83 r0 top locked
SW3 "PB SW" Switch-PB-6.2x6.3mm-SMD 105.653,4.502 r180 top locked
SW4 "PB SW" Switch-PB-6.2x6.3mm-SMD 115.915,4.502 r180 top locked
SW5 "PB SW" Switch-PB-6.2x6.3mm-SMD 77.292,4.502 r180 top
SW6 "MKH-22D14-G2-B" MKH-22D14-G2-B 104.369,57.988 r180 top
SW7 "Switch" CJS-120xA 82.55,43.815 r0 top
SW8 "MKH-22D14-G2-B" MKH-22D14-G2-B 5.528,5.359 r0 top
SW9 "JS203011JCQN" Switch-Slide-J-Lead-DP3T-13x3.5mm 23.749,38.506 r0 top locked
SW10 "CAS-220TA" CAS-220TA 20.625,4.064 r180 top
TP1 "Ø1.0mm,SMD" TP_SMD_Ø1.0mm 65.786,19.05 r90 top
TP2 "Ø1.0mm,SMD" TP_SMD_Ø1.0mm 65.786,21.59 r90 top
TP3 "Ø1.0mm,SMD" TP_SMD_Ø1.0mm 68.326,19.05 r90 top
TP4 "Ø1.0mm,SMD" TP_SMD_Ø1.0mm 68.326,21.59 r90 top
TP5 "Ø1.0mm,SMD" TP_SMD_Ø1.0mm 53.34,16.51 r90 top
TP6 "Ø1.0mm,SMD" TP_SMD_Ø1.0mm 55.88,16.51 r90 top
TP7 "Ø1.0mm,SMD" TP_SMD_Ø1.0mm 53.34,19.05 r90 top
TP8 "Ø1.0mm,SMD" TP_SMD_Ø1.0mm 55.88,19.05 r90 top
TP9 "Ø1.0mm,SMD" TP_SMD_Ø1.0mm 12.344,31.901 r90 top
TP10 "Ø1.0mm,SMD" TP_SMD_Ø1.0mm 10.566,32.259 r90 top
TP11 "Ø1.0mm,SMD" TP_SMD_Ø1.0mm 10.16,35.56 r90 top locked
TP12 "Ø1.0mm,SMD" TP_SMD_Ø1.0mm 10.16,38.1 r90 top locked
TP13 "Ø1.5mm,SMD" TP_SMD_Ø1.5mm 93.294,16.129 r0 top
TP14 "Ø1.5mm,SMD" TP_SMD_Ø1.5mm 95.199,16.129 r0 top
TP15 "Ø1.5mm,SMD" TP_SMD_Ø1.5mm 91.389,16.129 r0 top
TP16 "Ø1.5mm,SMD" TP_SMD_Ø1.5mm 97.104,16.129 r0 top
TP17 "Ø1.0mm,SMD" TP_SMD_Ø1.0mm 123.444,18.415 r90 top
TP18 "Ø1.0mm,SMD" TP_SMD_Ø1.0mm 125.984,18.415 r90 top
TP19 "Ø1.0mm,SMD" TP_SMD_Ø1.0mm 62.484,27.94 r90 top
TP20 "Ø1.0mm,SMD" TP_SMD_Ø1.0mm 103.378,19.304 r0 top
TP21 "Ø1.0mm,SMD" TP_SMD_Ø1.0mm 103.378,21.209 r0 top
TP22 "Ø1.0mm,SMD" TP_SMD_Ø1.0mm 107.772,48.311 r0 top
TP23 "Ø1.0mm,SMD" TP_SMD_Ø1.0mm 77.216,43.18 r0 top
TP24 "Ø1.0mm,SMD" TP_SMD_Ø1.0mm 10.795,45.847 r0 top
TP25 "Ø1.0mm,SMD" TP_SMD_Ø1.0mm 10.795,48.387 r0 top
TP26 "Ø1.0mm,SMD" TP_SMD_Ø1.0mm 1.27,38.1 r0 top
TP27 "Ø1.0mm,SMD" TP_SMD_Ø1.0mm 12.827,16.51 r0 top
TP28 "Ø1.0mm,SMD" TP_SMD_Ø1.0mm 14.757,22.682 r0 top
TP29 "Ø1.0mm,SMD" TP_SMD_Ø1.0mm 22.352,16.383 r0 top
TP30 "Ø1.0mm,SMD" TP_SMD_Ø1.0mm 28.55,15.037 r270 top
TP31 "Ø1.0mm,SMD" TP_SMD_Ø1.0mm 21.59,30.988 r90 top
TP32 "Ø1.0mm,SMD" TP_SMD_Ø1.0mm 21.59,29.21 r0 top
TP33 "Ø1.0mm,SMD" TP_SMD_Ø1.0mm 31.496,37.338 r0 top
TP34 "Ø1.0mm,SMD" TP_SMD_Ø1.0mm 28.702,17.78 r0 top
TP35 "Ø1.0mm,SMD" TP_SMD_Ø1.0mm 61.722,39.624 r0 top
TP36 "Ø1.0mm,SMD" TP_SMD_Ø1.0mm 69.215,38.1 r0 top
TP37 "Ø1.0mm,SMD" TP_SMD_Ø1.0mm 71.755,15.24 r0 top
TP38 "Ø1.0mm,SMD" TP_SMD_Ø1.0mm 86.36,15.24 r0 top
TP39 "Ø1.0mm,SMD" TP_SMD_Ø1.0mm 69.215,40.005 r0 top
TP40 "TP" TESTPAD-TH 114.702,20.938 r0 top
TP41 "TP" TESTPAD-TH 67.945,5.715 r0 top
TP42 "Ø1.0mm,SMD" TP_SMD_Ø1.0mm 95.885,25.781 r0 top
TP43 "Ø1.0mm,SMD" TP_SMD_Ø1.0mm 95.885,27.686 r0 top
TP44 "Ø1.0mm,SMD" TP_SMD_Ø1.0mm 97.79,25.781 r0 top
TP45 "Ø1.0mm,SMD" TP_SMD_Ø1.0mm 97.79,27.686 r0 top
TP46 "Ø1.0mm,SMD" TP_SMD_Ø1.0mm 99.695,25.781 r0 top
TP47 "Ø1.0mm,SMD" TP_SMD_Ø1.0mm 99.695,27.686 r0 top
TP48 "Ø1.0mm,SMD" TP_SMD_Ø1.0mm 129.422,58.179 r0 top
TP49 "Ø1.0mm,SMD" TP_SMD_Ø1.0mm 125.362,49.929 r270 top
TP50 "Ø1.0mm,SMD" TP_SMD_Ø1.0mm 115.519,62.052 r0 top
U1 "nRF52840-QIAA" AQFN50P700X700X85_HS-74N 115.164,37.617 r0 top locked
U2 "ATSAM3U2CA-AU" TSQFP50P1600X1600X160-100N 43.754,25.4 r90 top locked
U3 "74LVC1G11" SOT65P210X100-6N 21.065,9.644 r90 top
U4 "SC728CSTRT" BGA4C40P2X2_76X76X62 107.744,52.676 r180 top
U5 "FSA2466UMX" XQFN40P180X260X50-16N 73.939,19.71 r90 top
U6 "FSA2466UMX" XQFN40P180X260X50-16N 59.792,18.567 r180 top
U7 "FSA2466UMX" XQFN40P180X260X50-16N 81.94,19.71 r90 top locked
U8 "FSA2466UMX" XQFN40P180X260X50-16N 91.948,23.622 r180 top locked
U9 "SKY66112-11" SKY66112-11 127.128,38.63 r90 top
U10 "ISL9123" BGA8C40P2X4_100X180X55 113.297,60.1 r0 top
U11 "XC9236" USP-6C 20.726,20.218 r0 top
U12 "XC9131" "10-USPB (2.9x2.6)" 12.344,26.264 r180 top
U13 "SC728CSTRT" BGA4C40P2X2_76X76X62 20.371,16.053 r0 top
U14 "SC728CSTRT" BGA4C40P2X2_76X76X62 20.371,14.376 r270 top
U15 "SC728CSTRT" BGA4C40P2X2_76X76X62 20.371,12.7 r0 top
U16 "SC728CSTRT" BGA4C40P2X2_76X76X62 25.578,17.882 r180 top
U17 "SC728CSTRT" BGA4C40P2X2_76X76X62 23.317,17.882 r180 top
U18 "SC728CSTRT" BGA4C40P2X2_76X76X62 30.119,17.186 r180 top
U19 "TS27L2IPT" TSOP65P640X120-8N 24.943,25.781 r0 top
U20 "74LVC1G08" SOT65P210X100-5N 25.298,14.605 r180 top
U21 "74LVC1G11" SOT65P210X100-6N 18.237,9.652 r90 top
U22 "TCK106AF" SOT95P280X140-5N 84.303,12.548 r270 top
U23 "TCK106AF" SOT95P280X140-5N 49.86,42.189 r180 top
U24 "SC728CSTRT" BGA4C40P2X2_76X76X62 27.483,30.353 r270 top
U25 "74LVC1G08" SOT65P210X100-5N 23.923,9.643 r90 top
U26 "AP2127" SOT95P282X145-5N 127.648,53.917 r270 top
X1 "32MHz" BT-XTAL_2016 119.425,43.713 r180 top
X2 "32.768kHz" XTAL_3215 108.671,38.525 r0 top
X20 "12MHz" BT-XTAL_3225 36.769,36.728 r180 top

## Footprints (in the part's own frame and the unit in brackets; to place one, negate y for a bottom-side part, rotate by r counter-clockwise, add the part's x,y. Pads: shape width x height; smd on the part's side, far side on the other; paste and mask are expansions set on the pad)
"10-USPB (2.9x2.6)" [mm] "PQFN, 10-Leads, Body 2.60x2.90mm, Pitch 0.50mm, Thermal Pad 1.60x2.50mm, IPC Medium Density"
  rect 0.45x0.475 smd paste-0.088 mask+0.07: 1(-1.27,1.15) 2(-1.27,0.5) 9(1.27,0.5) 10(1.27,1.15)
  rect 0.45x0.25 smd paste-0.05 mask+0.07: 3(-1.27,-0.15) 4(-1.27,-0.65) 5(-1.27,-1.15) 6(1.27,-1.15) 7(1.27,-0.65) 8(1.27,-0.15)
  rect 1.6x2.5 smd paste-5: 11(0,0)
  silkscreen extent -1.95,-1.53 1.35,2.1, body extent -1.3,-1.45 1.3,1.45, height 0.6
2450AT18B100#1 [mm] "2450MHz Antenna"
  rect 0.8x1.85 smd: 1(-1.7,0) 2(1.7,0)
  Multi-Layer pour cut-out: -4.165,-9.003 -4.165,8.639 6.09,8.639 6.09,-9.003
  silkscreen extent -1.18,-0.14 -0.34,0.14, body extent -1.7,-0.9 1.7,0.9, height 1.4
2450AT18B100#2 [mm] "2450MHz Antenna"
  rect 0.8x1.85 smd: 1(-1.7,0) 2(1.7,0)
  Multi-Layer pour cut-out: -4.169,-9.276 -4.169,9.977 9.748,9.977 9.748,-9.276
  silkscreen extent -1.18,-0.13 -0.34,0.14, body extent -1.7,-0.9 1.7,0.9, height 1.4
AQFN50P700X700X85_HS-74N [mm] "AQFN, 73-Leads, Body 7.00x7.00mm, Pitch 0.50mm, Thermal Pad 4.95x4.95mm, IPC Medium Density"
  rect 4.85x4.85 smd mask+0.05: 74(0,0)
  round 0.275 smd paste+0.012 mask+0.05: A8(-1.25,3.25) A10(-0.75,3.25) A12(-0.25,3.25) A14(0.25,3.25) A16(0.75,3.25) A18(1.25,3.25) A20(1.75,3.25) A22(2.25,3.25) A23(2.75,3.25) AA24(3.25,-2.25) AB2(-2.75,-2.5) AC5(-2,-2.75) AC9(-1,-2.75) AC11(-0.5,-2.75) AC13(0,-2.75) AC15(0.5,-2.75) AC17(1,-2.75) AC19(1.5,-2.75) AC21(2,-2.75) AC24(3.25,-2.75) AD2(-2.75,-3.25) AD4(-2.25,-3.25) AD6(-1.75,-3.25) AD8(-1.25,-3.25) AD10(-0.75,-3.25) AD12(-0.25,-3.25) AD14(0.25,-3.25) AD16(0.75,-3.25) AD18(1.25,-3.25) AD20(1.75,-3.25) AD22(2.25,-3.25) AD23(2.75,-3.25) B1(-3.25,2.75) B3(-2.5,2.75) B5(-2,2.75) B7(-1.5,2.75) B9(-1,2.75) B11(-0.5,2.75) B13(0,2.75) B15(0.5,2.75) B17(1,2.75) B19(1.5,2.75) B24(3.25,2.75) C1(-3.25,2.25) D2(-2.75,2) D23(2.75,2) E24(3.25,1.75) F2(-2.75,1.5) F23(2.75,1.5) G1(-3.25,1.25) H2(-2.75,1) H23(2.75,1) J1(-3.25,0.75) J24(3.25,0.75) K2(-2.75,0.5) L1(-3.25,0.25) L24(3.25,0.25) M2(-2.75,0) N1(-3.25,-0.25) N24(3.25,-0.25) P2(-2.75,-0.5) P23(2.75,-0.5) R1(-3.25,-0.75) R24(3.25,-0.75) T2(-2.75,-1) T23(2.75,-1) U1(-3.25,-1.25) U24(3.25,-1.25) V23(2.75,-1.5) W1(-3.25,-1.75) W24(3.25,-1.75) Y2(-2.75,-2) Y23(2.75,-2)
  silkscreen extent -4.56,-3.6 3.6,3.6, body extent -3.55,-3.55 3.55,3.55, height 0.85
BGA4C40P2X2_76X76X62 [mm] "BGA, 4-Leads, Body 0.8x0.8mm,  Pitch 0.40mm"
  round 0.22 smd mask+0.06: A1(-0.2,0.2) A2(0.2,0.2) B1(-0.2,-0.2) B2(0.2,-0.2)
  silkscreen extent -0.74,-0.45 0.45,0.74, body extent -0.38,-0.38 0.38,0.38, height 0.63
BGA8C40P2X4_100X180X55 [mm] "BGA, 8-Leads, Body 1.00x1.80mmx0.55mm, Pitch 0.40mm"
  round 0.21 smd: A1(-0.2,0.6) A2(0.2,0.6) B1(-0.2,0.2) B2(0.2,0.2) C1(-0.2,-0.2) C2(0.2,-0.2) D1(-0.2,-0.6) D2(0.2,-0.6)
  silkscreen extent -0.65,0.96 -0.56,1.05, body extent -0.5,-0.9 0.5,0.9, height 0.55
BT-XTAL_2016 [mm] "Crystal 2.0 x 1.6 mm"
  rect 0.95x0.85 smd: 1(-0.725,-0.575) 2(0.725,-0.575) 3(0.725,0.575) 4(-0.725,0.575)
  silkscreen extent -1.08,-0.88 1.08,0.88, body extent -1.05,-0.85 1.05,0.85, height 0.56
BT-XTAL_3225 [mm] "Mercury X32 series"
  rect 1.2x1.1 smd: 1(-1.194,-0.89) 2(1.194,-0.89) 3(1.194,0.891) 4(-1.194,0.891)
  silkscreen extent -1.8,-1.52 1.8,1.52, body extent -1.6,-1.25 1.6,1.25, height 0.6
CAPC0603X03L_C [mm] "Chip Capacitor, 2-Leads, Body 0.6x0.3mm, IPC High Density"
  rect 0.27x0.3 smd: 1(-0.285,0) 2(0.285,0)
  silkscreen extent -0.49,-0.22 0.49,0.22, body extent -0.3,-0.15 0.31,0.15, height 0.3
CAPC1005X04L [mm] "Chip Capacitor, 2-Leads, Body 1.0x0.5mm, IPC High Density"
  rect 0.6x0.5 smd: 1(-0.5,0) 2(0.5,0)
  silkscreen extent -0.9,-0.35 0.9,0.35, body extent -0.51,-0.25 0.51,0.25, height 0.5
CAPC1608X06L [mm] "Chip Capacitor, 2-Leads, Body 1.6x0.8mm, IPC High Density"
  rect 0.75x0.8 smd: 1(-0.675,0) 2(0.675,0)
  silkscreen extent -1.17,-0.5 1.17,0.5, body extent -0.8,-0.43 0.8,0.43, height 0.8
CAPC2012X11L [mm] "Chip Capacitor, 2-Leads, Body 2.0x1.3mm, IPC High Density"
  rect 1.1x1.4 smd: 1(-0.75,0) 2(0.75,0)
  silkscreen extent -1.43,-0.8 1.42,0.8, body extent -1,-0.62 1,0.63, height 0.77
CAS-220TA [mm] "SLIDE SWITCH DPDT J HOOK"
  rect 1x1.6 smd: 1(-1.75,-1.85) 2(0,-1.85) 3(1.75,-1.85) 4(-1.75,1.85) 5(0,1.85) 6(1.75,1.85)
  silkscreen extent -2.8,-2.6 2.7,2, body extent -2.7,-2.15 2.7,2.16, height 2.51
CJS-120xA [mm] "Slide Switches - SPDT, SMD, ON-ON"
  rect 1x1.6 smd: 1(1.75,-1.15) 2(0,1.15) 3(-1.75,-1.15)
  silkscreen extent -3,-1.25 3,1.25, body extent -3,-1.4 3,1.45, height 2.5
COAXIAL-SWF [mm]
  rect 0.5x0.58 smd: 1(0,1.16) 3(0,-1.16)
  rect 0.75x0.8 smd: 2(-1.025,0.95) 2(-1.025,-0.95) 2(1.025,0.95) 2(1.025,-0.95)
  Top Layer pour cut-out: -0.65,0.55 0.65,0.55 0.65,1.35 -0.65,1.35
  Top Layer pour cut-out: 0.65,-0.55 -0.65,-0.55 -0.65,-1.35 0.65,-1.35
  silkscreen extent -1.25,-1.25 1.25,1.25, body extent -1.26,-1.3 1.26,1.3, height 1.55
CR2032_HOLDER_SMD [mm] "CR2032 - SMD mount coin cell bat holder"
  round 18 on Bottom Solder paste+0: 0(0,0)
  rect 5.08x5.08 smd: 1(-13.081,0) 1(13.081,0)
  rrect50% 10x10 smd paste-9: 2(0,0)
  Top Layer circle w5: c0,0 r6.5
  silkscreen extent -10.54,-9.53 10.54,11.43, body extent -15.37,-10.27 15.37,9.78, height 3.96
DFN65P100X40-3L [mm] "DFN, 3-Leads, Body 0.60x1.00mm, Pitch 0.65mm, IPC High Density"
  rect 0.4x0.25 smd: 1(-0.35,0.225) 2(-0.35,-0.225)
  rect 0.4x0.7 smd: 3(0.35,0)
  silkscreen extent -0.57,0.58 -0.48,0.67, body extent -0.53,-0.33 0.53,0.33, height 0.4
DMC3730UFL3-7 [mm] "X2-DFN, 6-Leads, Body 1.00x1.30mm, Pitch 0.35mm, IPC Medium Density"
  rect 0.375x0.2 smd mask+0.06: 1(-0.407,0.53) 2(-0.407,0.18) 4(0.408,-0.53) 5(0.408,-0.18)
  rect 0.52x0.52 smd mask+0.06: 3(-0.2,-0.35) 6(0.2,0.35)
  silkscreen extent -0.89,-0.71 0.59,0.71, body extent -0.53,-0.65 0.53,0.65, height 0.35
DO-216AA [mm]
  rect 0.762x1.27 smd: 1(1.65,0)
  rect 2.67x2.54 smd: 3(-0.7,0)
  silkscreen extent -1.6,-1.05 0.7,1.05, body extent -1.9,-1 1.95,1, height 1.01
Fiducial [mm] "Fiducial Mark"
  round 1 smd paste+0 mask+0.5: 0(0,0)
  round 1 smd far side paste+0 mask+0.5: 0(0,0)
  Top Layer keep-out circle w0.01: c0,0 r1
  Bottom Layer keep-out circle w0.01: c0,0 r1
FPC_05P-0.5mm-RA-SMD [mm] "FPC, 5-Leads, Pitch 0,5mm"
  rect 0.6x2.6 smd: 0(-0.9,-2.3) 0(2.9,-2.3)
  rect 0.3x0.8 smd: 1(0,0) 2(0.5,0) 3(1,0) 4(1.5,0) 5(2,0)
  silkscreen extent -1.45,-3.85 3.45,0, body extent -1.3,-3.85 3.3,0.2, height 1.2
HDR_2x3-SMD [mil] "Board-Board Conn, Header, 6-way, 2-row"
  rect 50x150 smd: 1(-100,-87.5) 2(-100,87.5) 3(0,-87.5) 4(0,87.5) 5(100,-87.5) 6(100,87.5)
  silkscreen extent -160,-140 150,100, body extent -150,-148 150,148, height 382
HDR_2x5-SMD-1.27mm-K [mm] "SMT MICRO HEADER, (1,27) .050\" Keying Shroud"
  rect 0.76x2.4 smd: 1(-2.54,-1.95) 2(-2.54,1.95) 3(-1.27,-1.95) 4(-1.27,1.95) 5(0,-1.95) 6(0,1.95) 7(1.27,-1.95) 8(1.27,1.95) 9(2.54,-1.95) 10(2.54,1.95)
  silkscreen extent -3.18,-3.15 3.18,3.15, body extent -3.14,-2.92 3.14,2.92, height 6.11
HDR_2x6-NC [mm] "Pin Header, 2.54mm through hole"
  rect 1.5x1.5 hole 0.9: 1(-6.35,-1.27)
  round 1.5 hole 0.9: 2(-6.35,1.27) 3(-3.81,-1.27) 4(-3.81,1.27) 5(-1.27,-1.27) 6(-1.27,1.27) 7(1.27,-1.27) 8(1.27,1.27) 9(3.81,-1.27) 10(3.81,1.27) 11(6.35,-1.27) 12(6.35,1.27)
  silkscreen extent -7.62,-2.54 7.62,2.54
HDR_2x8-NC [mm] "Pin Header, 2.54mm through hole"
  rect 1.5x1.5 hole 0.9: 1(-8.89,-1.27)
  round 1.5 hole 0.9: 2(-8.89,1.27) 3(-6.35,-1.27) 4(-6.35,1.27) 5(-3.81,-1.27) 6(-3.81,1.27) 7(-1.27,-1.27) 8(-1.27,1.27) 9(1.27,-1.27) 10(1.27,1.27) 11(3.81,-1.27) 12(3.81,1.27) 13(6.35,-1.27) 14(6.35,1.27) 15(8.89,-1.27) 16(8.89,1.27)
  silkscreen extent -10.16,-2.54 10.16,2.54
HDR_2x10-NC [mm] "Pin Header, 2.54mm through hole"
  rect 1.5x1.5 hole 0.9: 1(-11.43,-1.27)
  round 1.5 hole 0.9: 2(-11.43,1.27) 3(-8.89,-1.27) 4(-8.89,1.27) 5(-6.35,-1.27) 6(-6.35,1.27) 7(-3.81,-1.27) 8(-3.81,1.27) 9(-1.27,-1.27) 10(-1.27,1.27) 11(1.27,-1.27) 12(1.27,1.27) 13(3.81,-1.27) 14(3.81,1.27) 15(6.35,-1.27) 16(6.35,1.27) 17(8.89,-1.27) 18(8.89,1.27) 19(11.43,-1.27) 20(11.43,1.27)
  silkscreen extent -12.7,-2.54 12.7,2.54
HDR_2x10-SMD-1.27mm-NC [mm] "SMT MICRO HEADER, (1,27) .050\""
  rect 0.76x2.4 smd paste-5: 1(-5.715,-1.95) 2(-5.715,1.95) 3(-4.445,-1.95) 4(-4.445,1.95) 5(-3.175,-1.95) 6(-3.175,1.95) 7(-1.905,-1.95) 8(-1.905,1.95) 9(-0.635,-1.95) 10(-0.635,1.95) 11(0.635,-1.95) 12(0.635,1.95) 13(1.905,-1.95) 14(1.905,1.95) 15(3.175,-1.95) 16(3.175,1.95) 17(4.445,-1.95) 18(4.445,1.95) 19(5.715,-1.95) 20(5.715,1.95)
  silkscreen extent -6.35,-3.15 6.35,3.15
INDC1005X04L [mm] "Chip Inductor, 2-Leads, Body 1.0x0.5mm, IPC High Density"
  rect 0.65x0.5 smd: 1(-0.475,0) 2(0.475,0)
  silkscreen extent -0.9,-0.35 0.9,0.35, body extent -0.5,-0.3 0.5,0.3, height 0.5
INDC1608X06L [mm] "Chip Inductor, 2-Leads, Body 1.6x0.8mm, IPC High Density"
  rect 0.75x0.8 smd: 1(-0.675,0) 2(0.675,0)
  silkscreen extent -1.17,-0.5 1.17,0.5, body extent -0.8,-0.48 0.8,0.48, height 0.8
LED_0603_G [mil] "SMD Super Bright LED, GREEN"
  rect 30x32 smd: 1(-27.5,0) 2(27.5,0)
  silkscreen extent -58,-20 48,20, body extent -32,-16 32,16, height 24
LED_DUAL_0606 [mm]
  rect 0.65x0.85 smd paste+0: 1(0.425,0.725) 2(-0.425,0.725) 3(0.425,-0.725) 4(-0.425,-0.725)
  silkscreen extent -0.75,-0.8 0.75,0.8, body extent -0.75,-0.8 0.75,0.8, height 0.55
LIST_1x2-NC [mm] "Pin List, 2.54mm through hole"
  rect 1.5x1.5 hole 0.9: 1(-1.27,0)
  round 1.5 hole 0.9: 2(1.27,0)
  silkscreen extent -2.54,-1.27 2.54,1.27
LIST_1x3-NC [mm] "Pin List, 2.54mm through hole"
  rect 1.5x1.5 hole 0.9: 1(-2.54,0)
  round 1.5 hole 0.9: 2(0,0) 3(2.54,0)
  silkscreen extent -3.81,-1.27 3.81,1.27
LIST_1x6_SMD-NC [mm] "Pin List, 2.54mm, SMD"
  rect 1.02x2.19 smd paste+0: 1(0,-1.465) 1(0,1.465) 2(2.54,-1.465) 2(2.54,1.465) 3(5.08,-1.465) 3(5.08,1.465) 4(7.62,-1.465) 4(7.62,1.465) 5(10.16,-1.465) 5(10.16,1.465) 6(12.7,-1.465) 6(12.7,1.465)
  silkscreen extent -1.27,-1.27 13.97,1.27
LIST_1x8_SMD-NC [mm] "Pin List, 2.54mm, SMD"
  rect 1.02x2.19 smd paste+0: 1(0,-1.465) 1(0,1.465) 2(2.54,-1.465) 2(2.54,1.465) 3(5.08,-1.465) 3(5.08,1.465) 4(7.62,-1.465) 4(7.62,1.465) 5(10.16,-1.465) 5(10.16,1.465) 6(12.7,-1.465) 6(12.7,1.465) 7(15.24,-1.465) 7(15.24,1.465) 8(17.78,-1.465) 8(17.78,1.465)
  silkscreen extent -1.27,-1.27 19.05,1.27
LIST_1x10_SMD-NC [mm] "Pin List, 2.54mm, SMD"
  rect 1.02x2.19 smd paste+0: 1(0,-1.465) 1(0,1.465) 2(2.54,-1.465) 2(2.54,1.465) 3(5.08,-1.465) 3(5.08,1.465) 4(7.62,-1.465) 4(7.62,1.465) 5(10.16,-1.465) 5(10.16,1.465) 6(12.7,-1.465) 6(12.7,1.465) 7(15.24,-1.465) 7(15.24,1.465) 8(17.78,-1.465) 8(17.78,1.465) 9(20.32,-1.465) 9(20.32,1.465) 10(22.86,-1.465) 10(22.86,1.465)
  silkscreen extent -1.27,-1.27 24.13,1.27
LIST_1x12_SMD [mm] "Pin List, 2.54mm, SMD"
  rect 1.02x2.19 smd: 1(0,-1.465) 1(0,1.465) 2(2.54,-1.465) 2(2.54,1.465) 3(5.08,-1.465) 3(5.08,1.465) 4(7.62,-1.465) 4(7.62,1.465) 5(10.16,-1.465) 5(10.16,1.465) 6(12.7,-1.465) 6(12.7,1.465) 7(15.24,-1.465) 7(15.24,1.465) 8(17.78,-1.465) 8(17.78,1.465) 9(20.32,-1.465) 9(20.32,1.465) 10(22.86,-1.465) 10(22.86,1.465) 11(25.4,-1.465) 11(25.4,1.465) 12(27.94,-1.465) 12(27.94,1.465)
  silkscreen extent -1.27,-1.27 29.21,1.27, body extent -1.27,-2.5 29.21,2.5, height 9.82
LIST_1x12_SMD-NC [mm] "Pin List, 2.54mm, SMD"
  rect 1.02x2.19 smd paste+0: 1(0,-1.465) 1(0,1.465) 2(2.54,-1.465) 2(2.54,1.465) 3(5.08,-1.465) 3(5.08,1.465) 4(7.62,-1.465) 4(7.62,1.465) 5(10.16,-1.465) 5(10.16,1.465) 6(12.7,-1.465) 6(12.7,1.465) 7(15.24,-1.465) 7(15.24,1.465) 8(17.78,-1.465) 8(17.78,1.465) 9(20.32,-1.465) 9(20.32,1.465) 10(22.86,-1.465) 10(22.86,1.465) 11(25.4,-1.465) 11(25.4,1.465) 12(27.94,-1.465) 12(27.94,1.465)
  silkscreen extent -1.27,-1.27 29.21,1.27
LIST_ANG_1x2-SMD-2.54MM [mm] "Pin List, 2.54mm, Surface Mount, Angled"
  round 1.78 hole 1.78 unplated: 0(0,-4.496)
  rect 1.27x3.18 smd: 1(-1.27,0) 2(1.27,0)
  silkscreen extent -2.54,-11.58 2.54,-1.8, body extent -2.56,-11.61 2.52,1.35, height 3.03
MKH-22D14-G2-B [mm] "Slide Switches - DPDT, SMD, ON-ON"
  rect 1.2x2 smd: 1(2.5,-2.75) 2(0,-2.75) 3(-2.5,-2.75) 4(2.5,2.75) 5(0,2.75) 6(-2.5,2.75)
  silkscreen extent -4.5,-3.75 4.5,1.75, body extent -4.25,-3.75 4.25,2.5, height 3.5
RESC0603X03L_C [mm] "Chip Resistor, 2-Leads, Body 0.6x0.3mm, IPC High Density"
  rect 0.27x0.3 smd: 1(-0.285,0) 2(0.285,0)
  silkscreen extent -0.49,-0.22 0.49,0.22, body extent -0.3,-0.15 0.3,0.15, height 0.23
RESC1005X04L [mm] "Chip Resistor, 2-Leads, Body 1.0x0.5mm, IPC High Density"
  rect 0.6x0.55 smd: 1(-0.5,0) 2(0.5,0)
  silkscreen extent -0.87,-0.38 0.88,0.38, body extent -0.5,-0.25 0.5,0.25, height 0.3
RESC3216X08N [mm] "Chip Resistor, 2-Leads, Body 3,20x1,60mm, IPC Medium Density"
  rect 1.35x1.8 smd: 1(-1.375,0) 2(1.375,0)
  silkscreen extent -0.3,-0.8 0.3,0.8, body extent -1.7,-0.9 1.7,0.9, height 0.8
SKY66112-11 [mm]
  rect 0.55x0.55 smd paste+0 mask+0.05: 1(-1.375,1.625) 7(-1.375,-1.625) 12(1.375,-1.625) 18(1.375,1.625)
  rect 0.55x0.3 smd paste+0 mask+0.05: 2(-1.375,1) 3(-1.375,0.5) 4(-1.375,0) 5(-1.375,-0.5) 6(-1.375,-1) 13(1.375,-1) 14(1.375,-0.5) 15(1.375,0) 16(1.375,0.5) 17(1.375,1)
  rect 0.3x0.55 smd paste+0 mask+0.05: 8(-0.75,-1.625) 9(-0.25,-1.625) 10(0.25,-1.625) 11(0.75,-1.625) 19(0.75,1.625) 20(0.25,1.625) 21(-0.25,1.625) 22(-0.75,1.625)
  rect 1.7x2.2 smd paste-2: 23(0,0)
  Top Layer region: -0.4,-1.1 -0.4,-1.9 0.4,-1.9 0.4,-1.1
  Top Layer region: 0.1,1.1 0.1,1.375 0.4,1.375 0.4,1.1 0.25,1.1
  Top Layer region: -0.6,1.1 -0.6,1.9 -1.65,1.9 -1.65,1.35 -1.1,1.35 -0.85,1.1
  Top Layer region: -0.85,-0.35 -0.85,-0.65 -1.65,-0.65 -1.65,-0.35
  Top Layer region: 0.85,-1.1 1.1,-1.35 1.65,-1.35 1.65,-1.125 1.65,-0.85 1.1,-0.85 0.85,-0.85
  silkscreen extent -1.82,-2.08 1.83,2.65, body extent -1.5,-1.65 1.5,1.65, height 0.9
SM02B-SRSS-TB [mm] "JST, SH connector, side entry SMD, 1mm pitch"
  rect 1.2x1.8 smd: 0(-2.1,-3.875) 0(2.1,-3.875)
  rect 0.6x1.55 smd: 1(-0.5,0) 2(0.5,0)
  silkscreen extent -2,-4.57 2,-0.33, body extent -1.99,-4.58 1.99,0.41, height 3
SOCKET_1x6_SMD [mm] "Socket, 2.54mm, SMD"
  rect 1.02x2.19 smd: 1(0,-1.465) 1(0,1.465) 2(2.54,-1.465) 2(2.54,1.465) 3(5.08,-1.465) 3(5.08,1.465) 4(7.62,-1.465) 4(7.62,1.465) 5(10.16,-1.465) 5(10.16,1.465) 6(12.7,1.465) 6(12.7,-1.465)
  silkscreen extent -1.27,-1.27 13.97,1.27, body extent -1.27,-2.29 13.97,2.29, height 7.47
SOCKET_1x8_SMD [mm] "Socket, 2.54mm, SMD"
  rect 1.02x2.19 smd: 1(0,-1.465) 1(0,1.465) 2(2.54,-1.465) 2(2.54,1.465) 3(5.08,-1.465) 3(5.08,1.465) 4(7.62,-1.465) 4(7.62,1.465) 5(10.16,-1.465) 5(10.16,1.465) 6(12.7,1.465) 6(12.7,-1.465) 7(15.24,-1.465) 7(15.24,1.465) 8(17.78,-1.465) 8(17.78,1.465)
  silkscreen extent -1.27,-1.27 19.05,1.27, body extent -1.27,-2.29 19.05,2.29, height 7.47
SOCKET_1x10_SMD [mm] "Socket, 2.54mm, SMD"
  rect 1.02x2.19 smd: 1(0,1.465) 1(0,-1.465) 2(2.54,-1.465) 2(2.54,1.465) 3(5.08,-1.465) 3(5.08,1.465) 4(7.62,-1.465) 4(7.62,1.465) 5(10.16,-1.465) 5(10.16,1.465) 6(12.7,-1.465) 6(12.7,1.465) 7(15.24,-1.465) 7(15.24,1.465) 8(17.78,-1.465) 8(17.78,1.465) 9(20.32,-1.465) 9(20.32,1.465) 10(22.86,-1.465) 10(22.86,1.465)
  silkscreen extent -1.27,-1.27 24.13,1.27, body extent -1.27,-2.29 24.13,2.29, height 7.47
SOCKET_2x3_SMD-2.54mm-bottom-NC [mm] "Socket, 2.54mm, SMD"
  rect 1.02x2.22 smd far side: 1(-2.54,-2.825) 2(-2.54,2.825) 3(0,-2.825) 4(0,2.825) 5(2.54,-2.825) 6(2.54,2.825)
SOCKET_2x9_SMD-2.54mm [mil] "CONN HEADER VERT DUAL 18POS SMD - FEMALE HEADER, PCB, 0.1\", 10+10WAY"
  rect 50x150 smd: 1(-400,-87.5) 2(-400,87.5) 3(-300,-87.5) 4(-300,87.5) 5(-200,-87.5) 6(-200,87.5) 7(-100,-87.5) 8(-100,87.5) 9(0,-87.5) 10(0,87.5) 11(100,-87.5) 12(100,87.5) 13(200,-87.5) 14(200,87.5) 15(300,-87.5) 16(300,87.5) 17(400,-87.5) 18(400,87.5)
  silkscreen extent -460,-140 450,100, body extent -450,-138 450,139, height 290
SODFL100X40-2N [mm] "SODFL, 2-Leads, Body 0.60x1.00mm, IPC Medium Density"
  rect 0.36x0.25 smd: 1(-0.42,0) 2(0.42,0)
  silkscreen extent -0.7,-0.35 0.5,0.5, body extent -0.5,-0.33 0.5,0.33, height 0.4
Solderbridge#1 [mm]
  round 0.2 smd paste-10: 1(-0.312,0) 2(0.312,0)
  Top Layer region: -0.077,-0.432 -0.152,-0.505 -0.271,-0.467 -0.335,-0.424 -0.409,-0.351 -0.462,-0.292 -0.521,-0.193 -0.549,-0.099 -0.544,0.122 -0.518,0.193 -0.434,0.33 -0.351,0.411 -0.259,0.469 -0.157,0.5 -0.107,0.483 -0.077,0.43
  Top Layer region: 0.077,0.432 0.152,0.505 0.271,0.467 0.335,0.424 0.409,0.351 0.462,0.292 0.521,0.193 0.549,0.099 0.544,-0.122 0.518,-0.193 0.434,-0.33 0.351,-0.411 0.259,-0.469 0.157,-0.5 0.107,-0.483 0.077,-0.43
  Top Layer lines w0.152: -0.153,0.431 ccw(c-0.042,0) -0.153,-0.431 ; 0.153,0.431 cw(c0.042,0) 0.487,0 cw(c0.042,0) 0.461,-0.149 cw(c0.042,0) 0.153,-0.431
Solderbridge#2 [mm]
  round 0.2 smd paste-10: 1(-0.312,0) 2(0.312,0)
  Top Layer region: -0.077,-0.432 -0.152,-0.505 -0.271,-0.467 -0.335,-0.424 -0.409,-0.351 -0.462,-0.292 -0.521,-0.193 -0.549,-0.099 -0.544,0.122 -0.518,0.193 -0.434,0.33 -0.351,0.411 -0.259,0.469 -0.157,0.5 -0.107,0.483 -0.077,0.43
  Top Layer region: 0.077,0.432 0.152,0.505 0.271,0.467 0.335,0.424 0.409,0.351 0.462,0.292 0.521,0.193 0.549,0.099 0.544,-0.122 0.518,-0.193 0.434,-0.33 0.351,-0.411 0.259,-0.469 0.157,-0.5 0.107,-0.483 0.077,-0.43
  Top Layer lines w0.152: -0.153,0.431 ccw(c-0.042,0) -0.153,-0.431 ; 0.153,0.431 cw(c0.042,0) 0.153,-0.431
Solderbridge#3 [mm]
  round 0.2 smd paste-10: 1(-0.312,0) 2(0.312,0)
  Top Layer region: -0.077,-0.432 -0.152,-0.505 -0.271,-0.467 -0.335,-0.424 -0.409,-0.351 -0.462,-0.292 -0.521,-0.193 -0.549,-0.099 -0.544,0.122 -0.518,0.193 -0.434,0.33 -0.351,0.411 -0.259,0.469 -0.157,0.5 -0.107,0.483 -0.077,0.43
  Top Layer region: 0.077,0.432 0.152,0.505 0.271,0.467 0.335,0.424 0.409,0.351 0.462,0.292 0.521,0.193 0.549,0.099 0.544,-0.122 0.518,-0.193 0.434,-0.33 0.351,-0.411 0.259,-0.469 0.157,-0.5 0.107,-0.483 0.077,-0.43
  Top Layer lines w0.152: 0.153,0.431 cw(c0.042,0) 0.153,-0.431 ; -0.153,0.431 ccw(c-0.042,0) -0.487,0 ccw(c-0.042,0) -0.153,-0.431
